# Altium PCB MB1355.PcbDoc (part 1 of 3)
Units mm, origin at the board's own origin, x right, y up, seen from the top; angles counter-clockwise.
Board outline 70.13 x 64.58 mm, 4 copper layers (L1, L2, L3, L4), stack 1.565 mm thick; 213 components, 161 nets, 1280 pads, 261 vias.
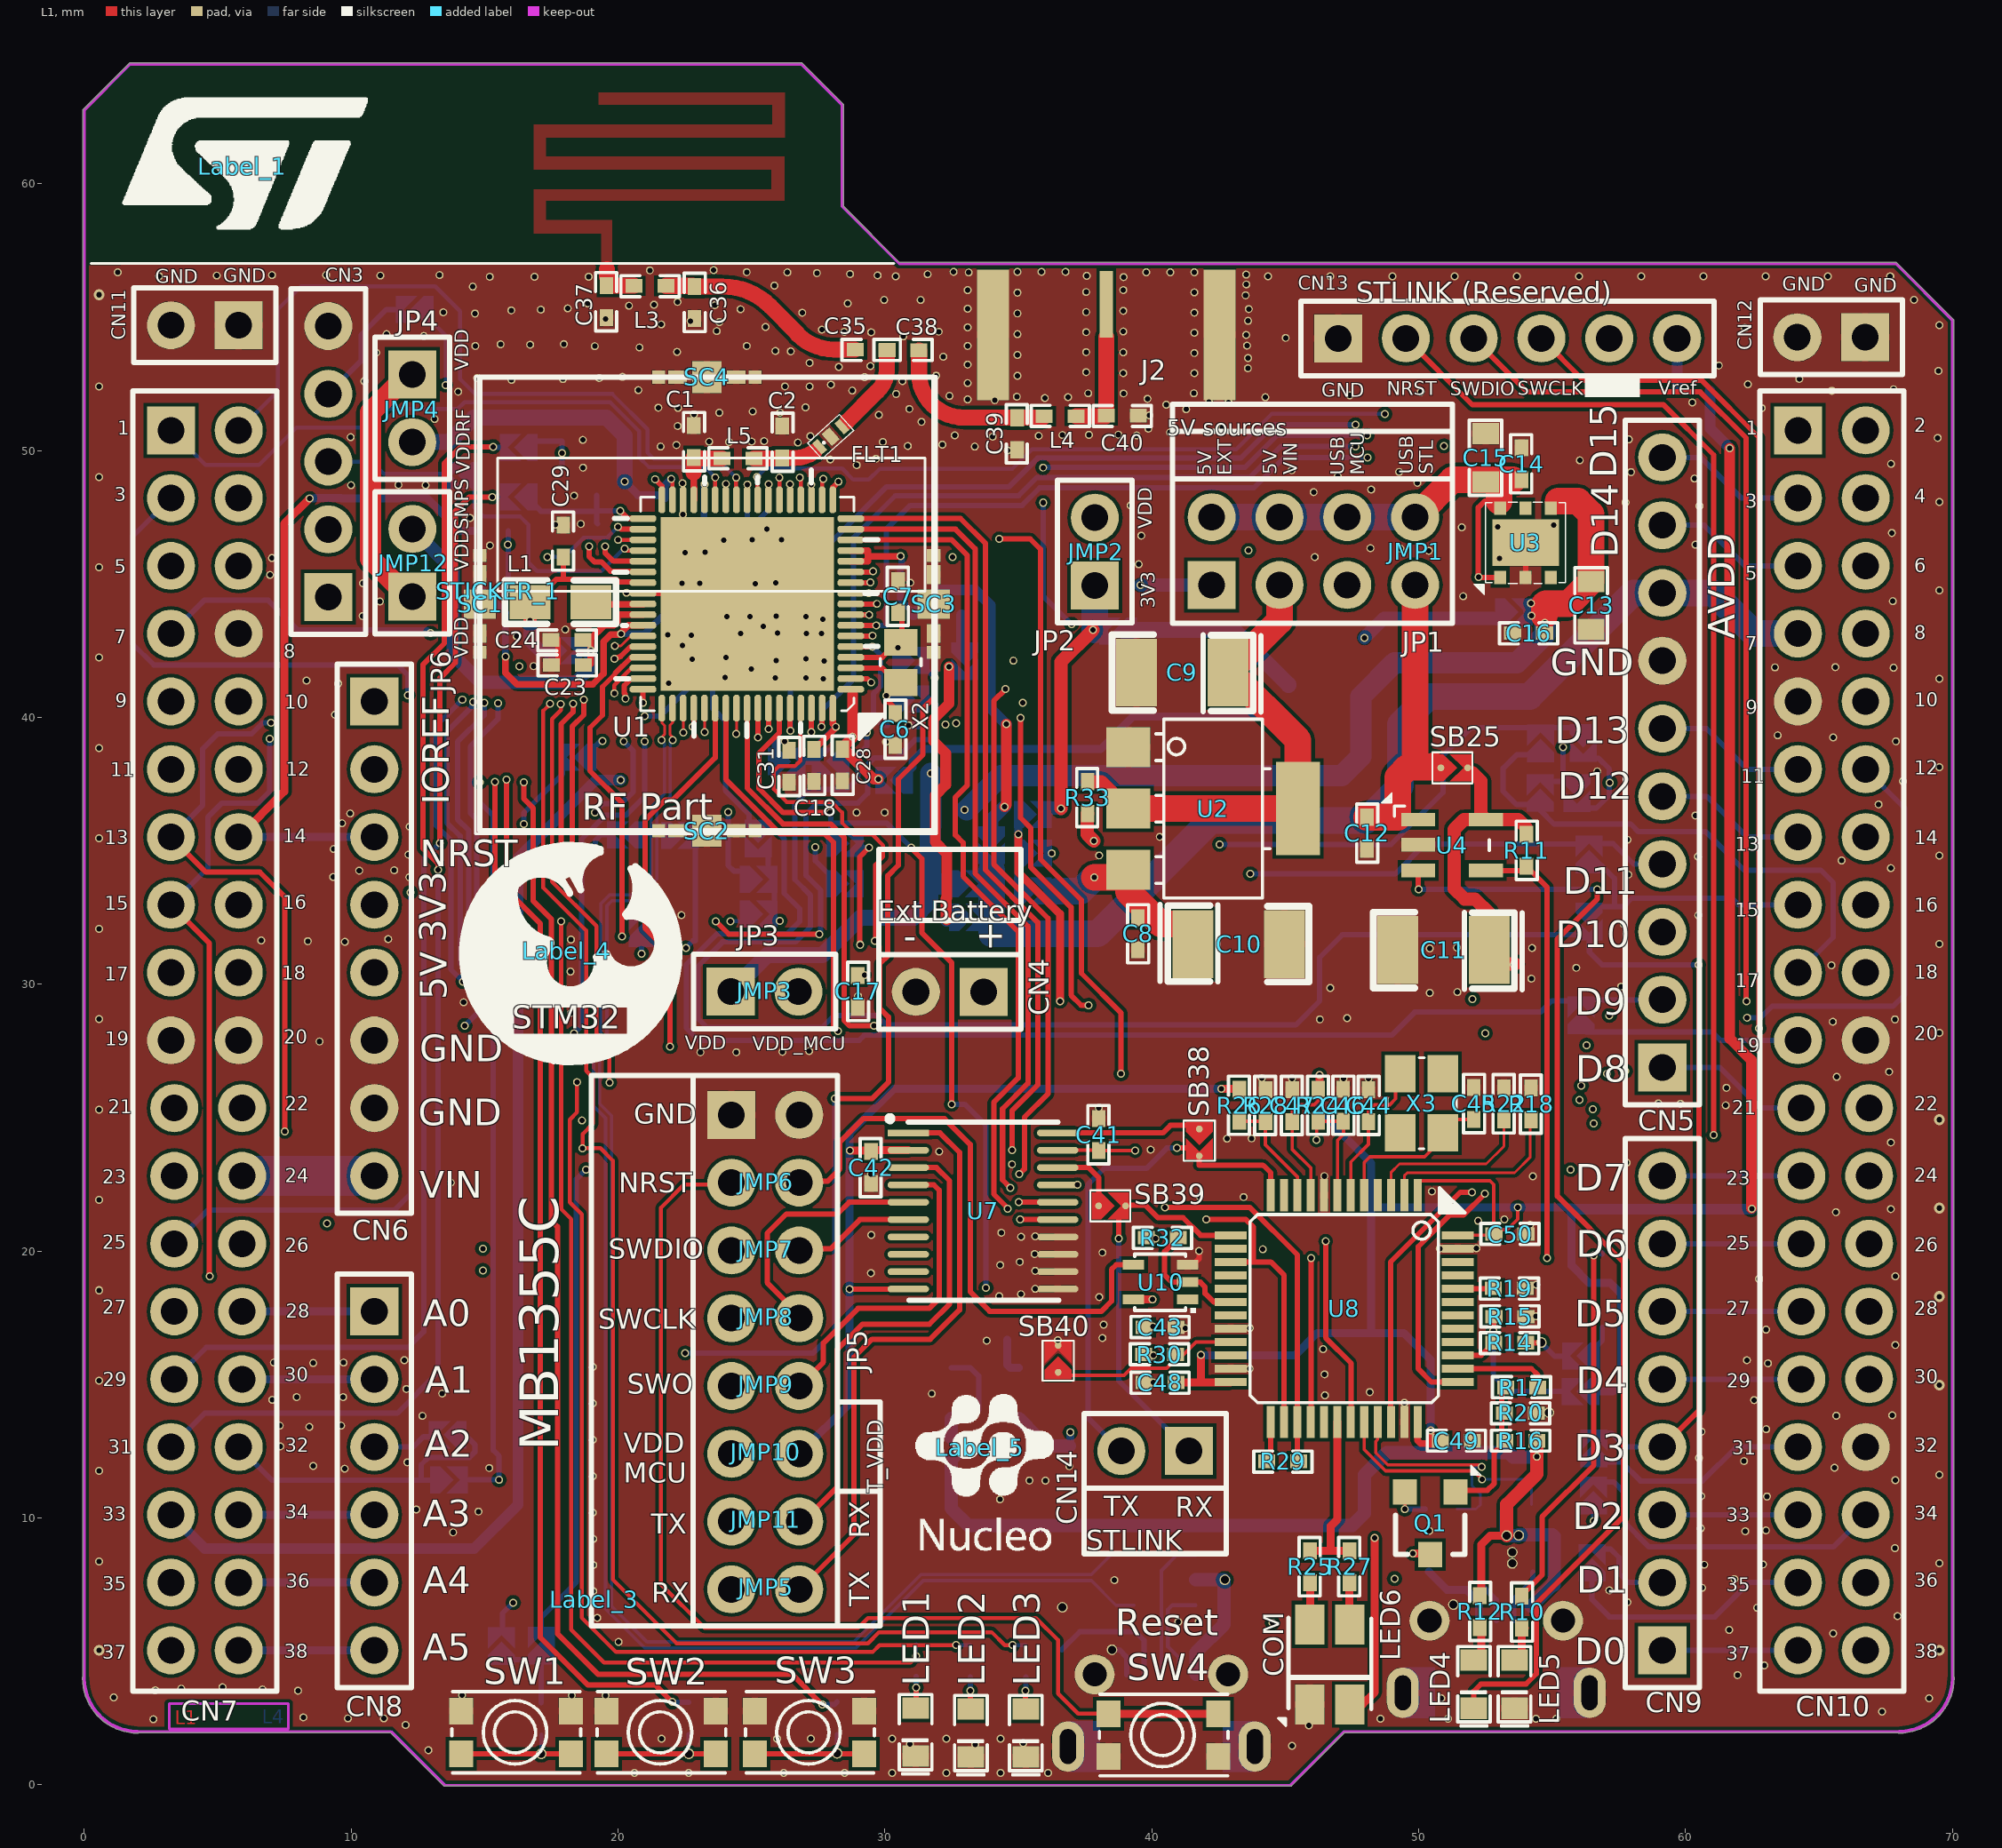
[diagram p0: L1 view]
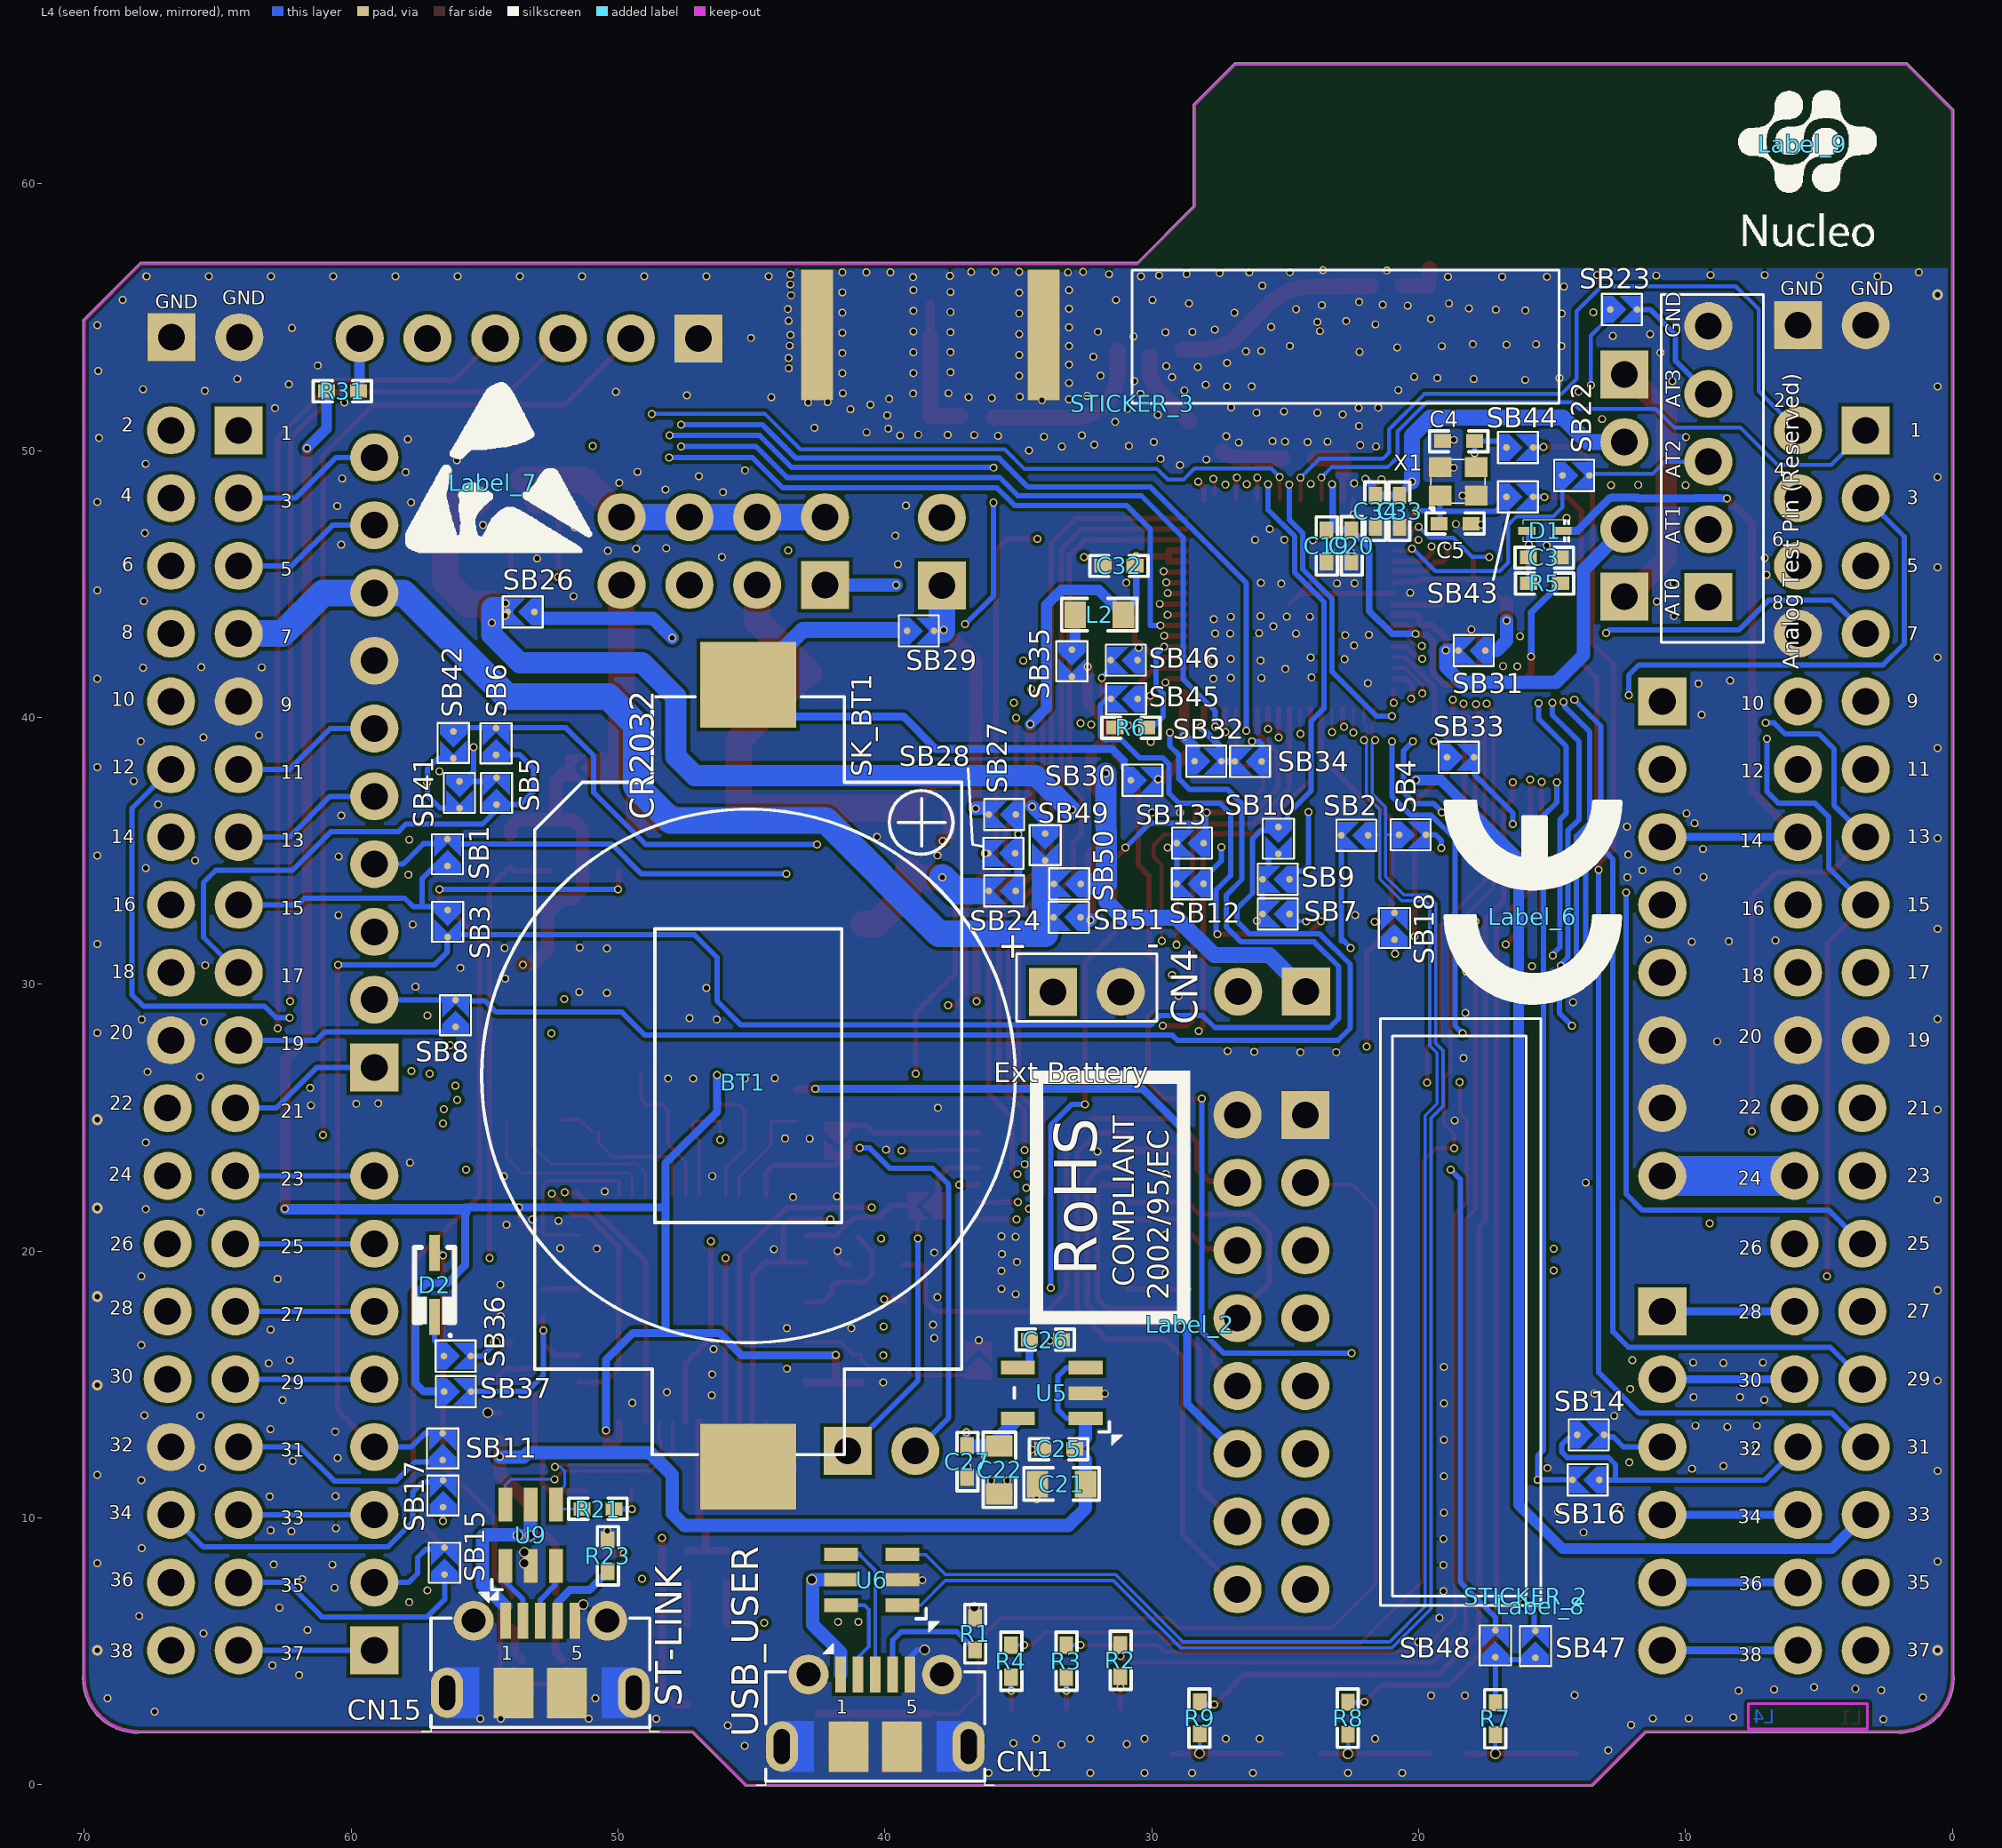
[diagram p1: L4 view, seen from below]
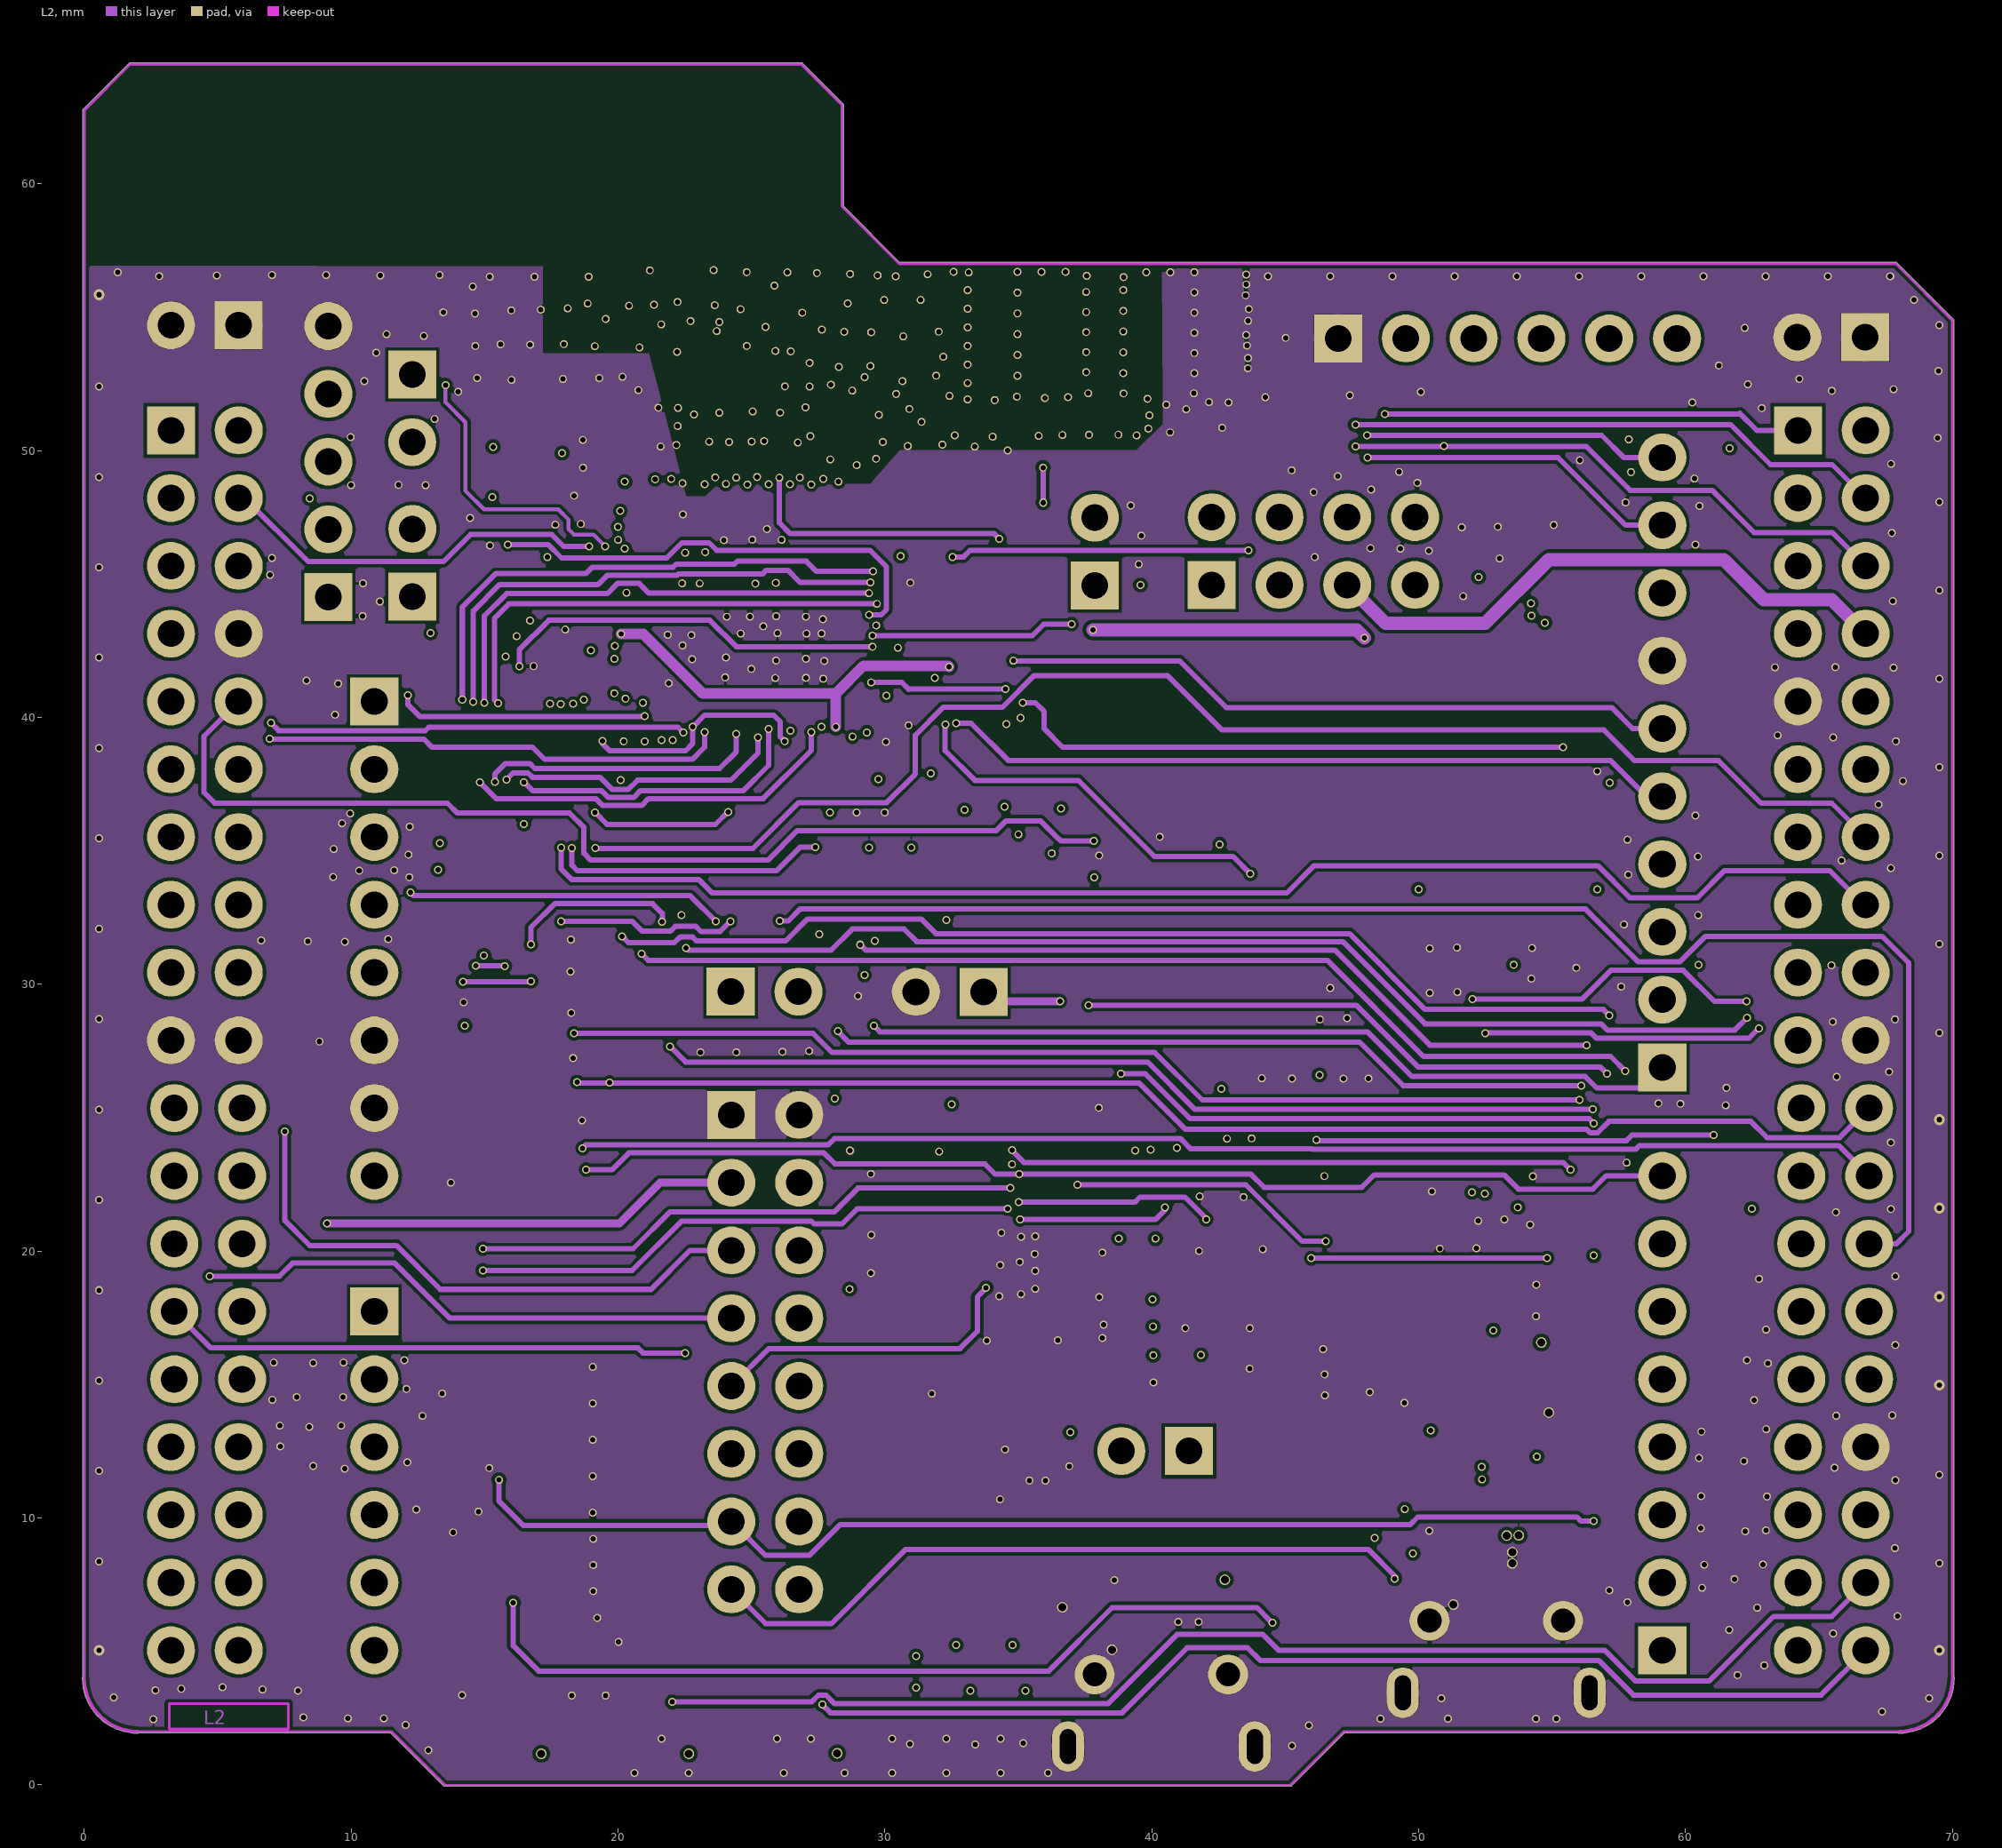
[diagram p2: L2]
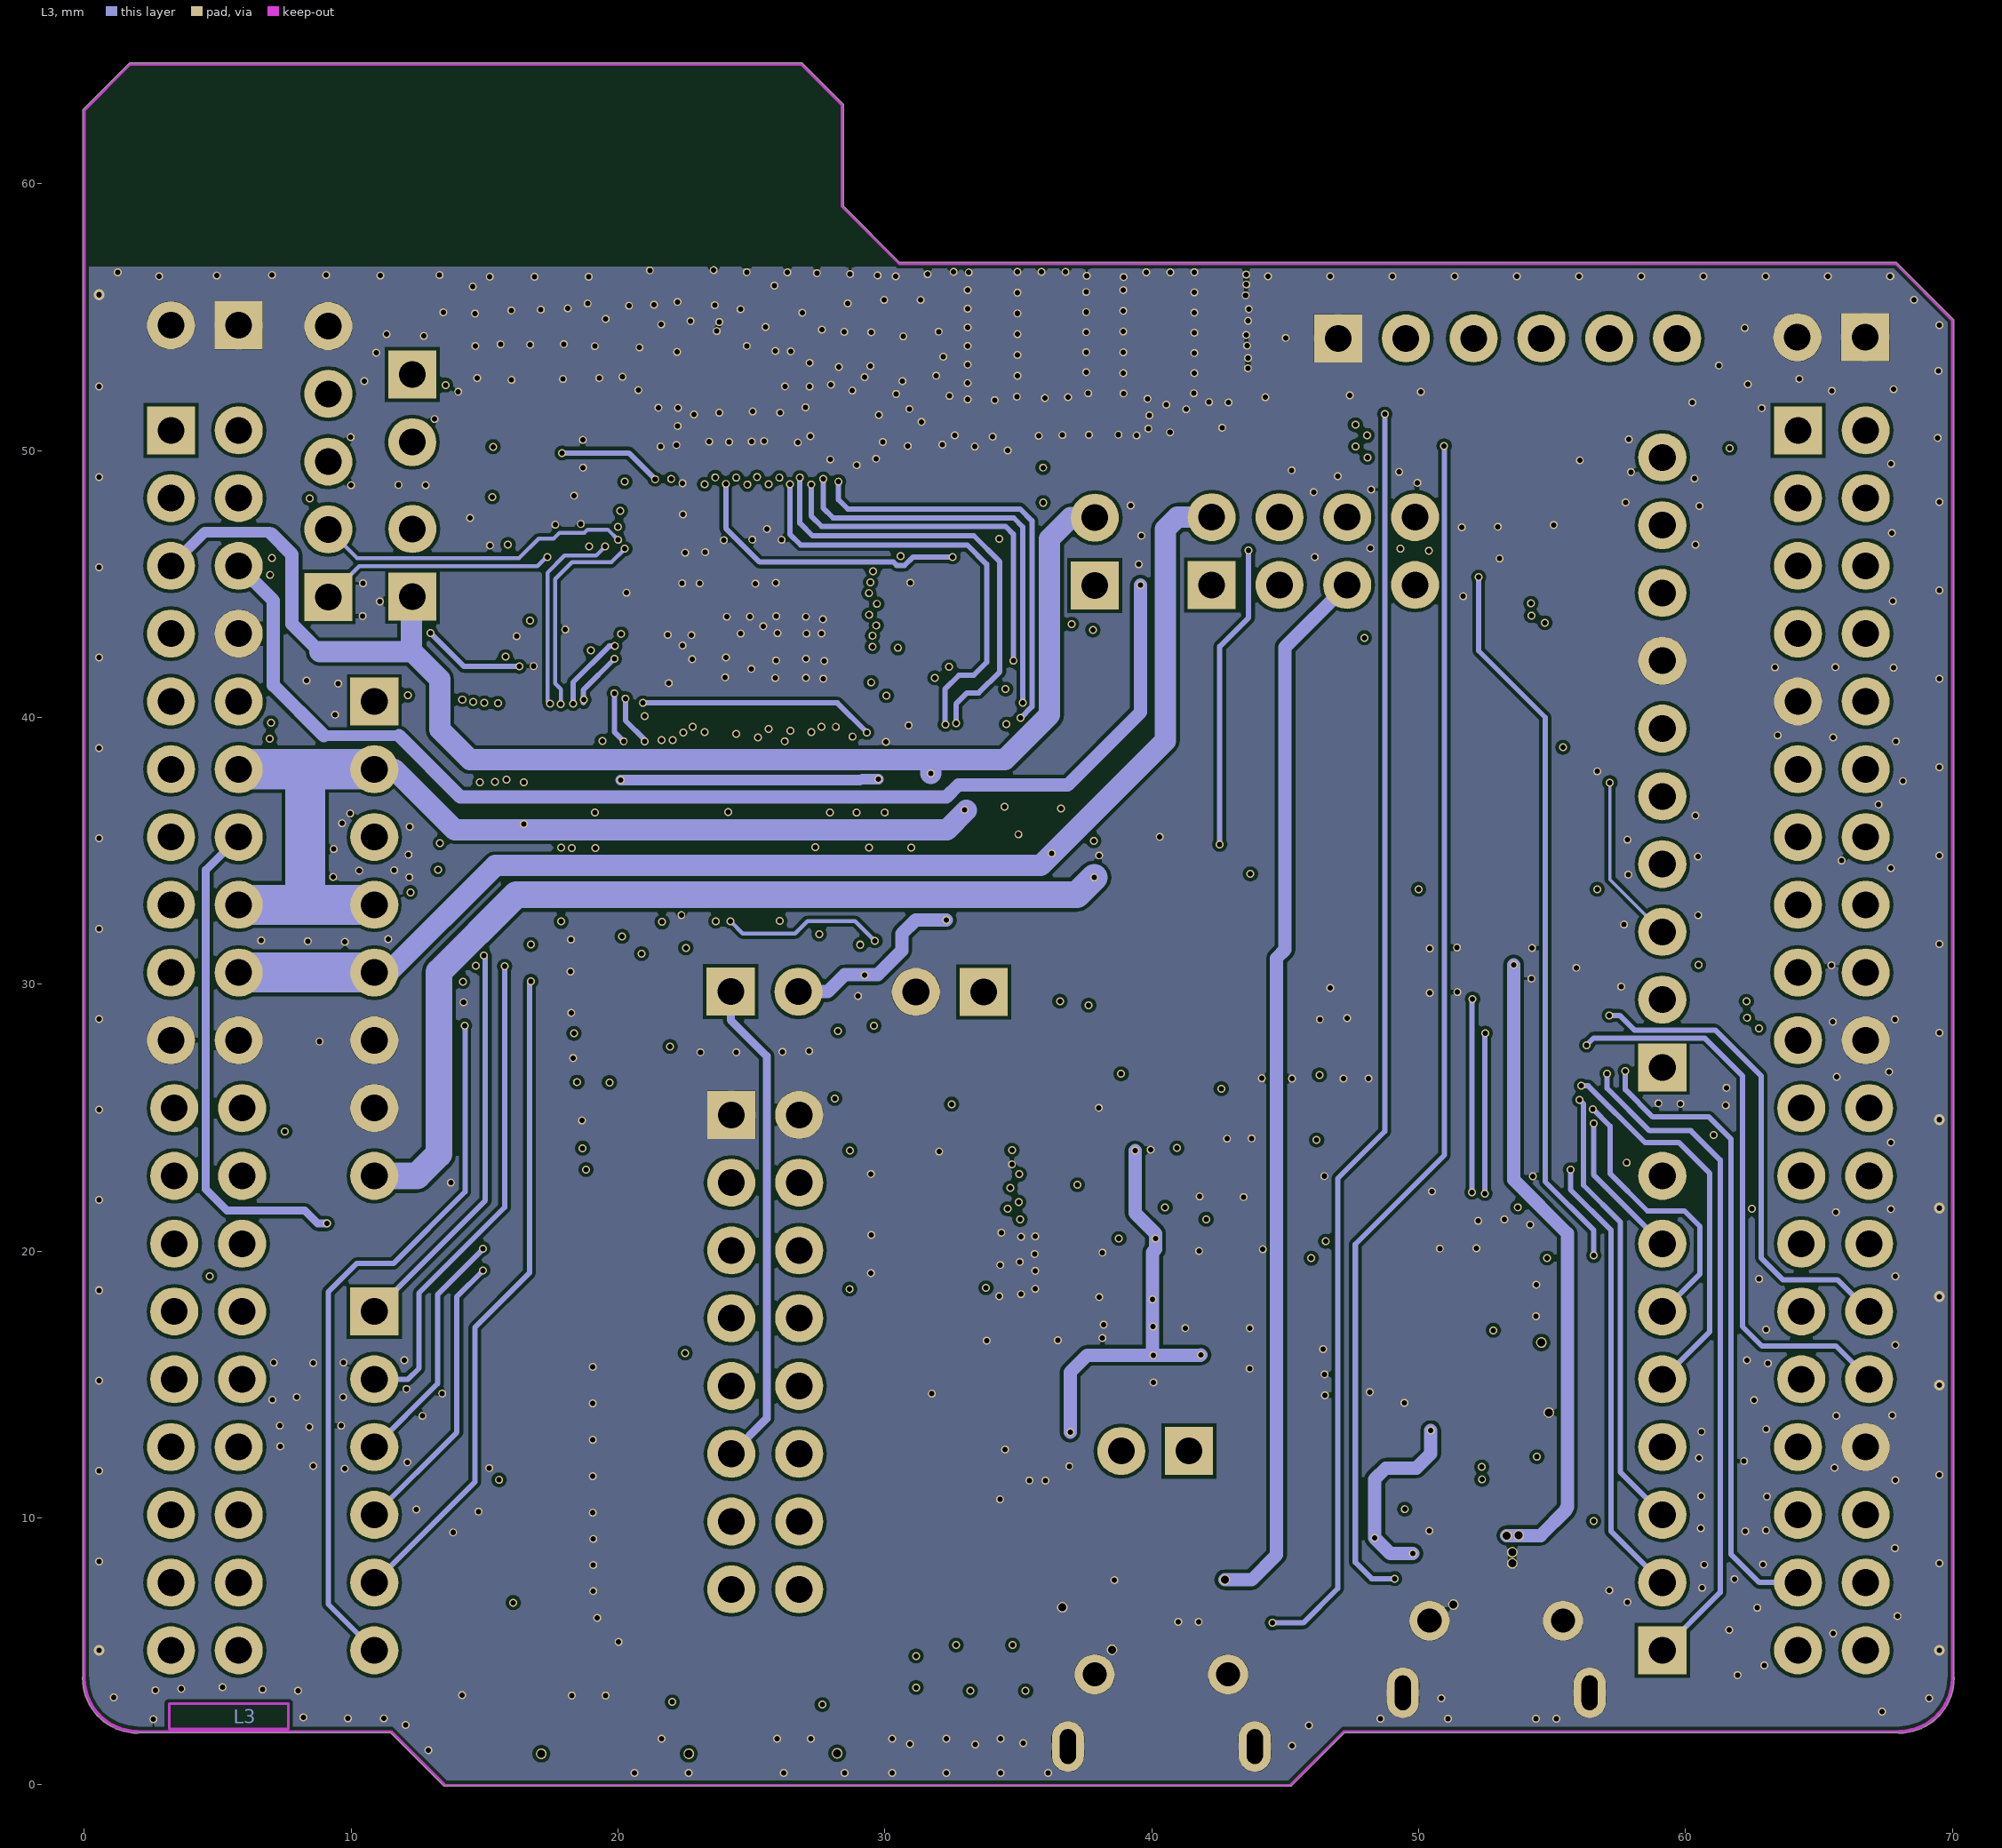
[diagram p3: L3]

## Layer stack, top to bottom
Top Solder: solder mask 0.0178, Solder Resist, Dk 4
L1: signal copper 0.0406
Dielectric1: core 0.4572, FR-4, Dk 4.2
L2: signal copper 0.0305
Dielectric 3: prepreg 0.508, Dk 4.4
L3: signal copper 0.0305
Dielectric 2: core 0.4572, FR-4, Dk 4.2
L4: signal copper 0.0406
Bottom Solder: solder mask 0.0178, Solder Resist, Dk 4

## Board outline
2,1.936 ccw(c2,2) 2.039,1.95 11.479,1.95 13.464,-0.036 13.464,-0.035 ccw(c13.5,0) 13.5,-0.05 45.2,-0.05 ccw(c45.2,0) 45.236,-0.035 45.236,-0.036 47.221,1.95 67.961,1.95 ccw(c68,2) 68,1.936 ccw(c68,4) 70.064,4 ccw(c70,4) 70.05,4.039 70.05,54.876 ccw(c70,54.876) 70.035,54.912 70.036,54.912 67.912,57.036 67.912,57.035 ccw(c67.876,57) 67.876,57.05 30.559,57.05 28.446,59.163 28.446,62.952 ccw(c28.396,62.952) 28.431,62.988 28.432,62.988 26.908,64.512 26.908,64.511 ccw(c26.872,64.476) 26.872,64.526 1.726,64.526 ccw(c1.726,64.476) 1.69,64.511 1.69,64.512 -0.036,62.786 -0.035,62.786 ccw(c0,62.75) -0.05,62.75 -0.05,4.039 ccw(c0,4) -0.064,4 ccw(c2,4)

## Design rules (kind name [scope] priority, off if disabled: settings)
AssemblyTestPointUsage [All] p1 off:
AssemblyTestpoint [All] p1 off: testpointundercomponent=TRUE minsize=1.016 maxsize=2.54 preferedsize=1.524 minholesize=0 maxholesize=1.016 preferedholesize=0.813 testpointgrid=0.025 usegrid=TRUE gridtolerance=0 allowsidetop=TRUE allowsidebottom=TRUE
Clearance 0.126 [All] p1: gap=0.1 ignorepadtopadclearanceinfootprint=FALSE except(0: Arc-Hole Track-Hole SMDPad-Hole THPad-Hole Via-Hole Fill-Hole Poly-Hole Region-Hole Text-Hole; 0.126: Arc-Poly Track-Poly SMDPad-Poly THPad-Poly Via-Poly)
ComponentClearance [All] p1 off: gap=0.254 collisioncheckmode=3 verticalgap=0.254 showdistances=FALSE
DiffPairsRouting [All] p1: maxlimit=0.1 minlimit=0.1 mostfreqgap=0.1 toplayer_minwidth=0.12 toplayer_maxwidth=0.12 toplayer_prefwidth=0.12 midlayer1_minwidth=0.12 midlayer1_maxwidth=0.12 midlayer1_prefwidth=0.12 midlayer4_minwidth=0.12 midlayer4_maxwidth=0.12 midlayer4_prefwidth=0.12 bottomlayer_minwidth=0.12 bottomlayer_maxwidth=0.12 bottomlayer_prefwidth=0.12 maxuncoupledlength=12.7
FabricationTestPointUsage TestPointUsage [All] p1 off: valid=0 allowmultiple=FALSE
FabricationTestpoint Testpoint [(IsPad And (OnTopLayer Or OnBottomLayer))] p1 off: side=3 testpointundercomponent=TRUE minsize=1.016 maxsize=2.54 preferedsize=1.524 minholesize=0 maxholesize=1.016 preferedholesize=0.813 testpointgrid=0.025 allowsidetop=TRUE allowsidebottom=TRUE usegrid=TRUE gridtolerance=0
FanoutControl Fanout_BGA [IsBGA] p1 off: bgadir=Out bgaviamode=Centered fanoutstyle=Auto fanoutdirection=Alternating viagrid=0.025 // Fanout_BGA (Default Rule)
FanoutControl Fanout_LCC [IsLCC] p2 off: bgadir=Out bgaviamode=Centered fanoutstyle=Auto fanoutdirection=Alternating viagrid=0.025 // Fanout_LCC (Default Rule)
FanoutControl Fanout_SOIC [IsSOIC] p3 off: bgadir=Out bgaviamode=Centered fanoutstyle=Auto fanoutdirection=Alternating viagrid=0.025 // Fanout_SOIC (Default Rule)
FanoutControl Fanout_Small [(CompPinCount < 5)] p4 off: bgadir=Out bgaviamode=Centered fanoutstyle=Auto fanoutdirection=OutThenIn viagrid=0.025 // Fanout_Small (Default Rule)
FanoutControl Fanout_Default [All] p5 off: bgadir=Out bgaviamode=Centered fanoutstyle=Auto fanoutdirection=Alternating viagrid=0.025 // Fanout_Default (Default Rule)
Height [All] p1 off: minheight=0 maxheight=25.4 prefheight=12.7
HoleSize [All] p1 off: absolutevalues=TRUE maxlimit=3.81 minlimit=0.1 maxpercent=80.000 minpercent=20.000
HoleToHoleClearance [All] p1 off: gap=0.254 allowstackedmicrovias=TRUE
LayerPairs [All] p1 off: enforce=FALSE
MinimumSolderMaskSliver [All] p1 off: minsoldermaskwidth=0.254
NetAntennae [All] p1 off: netantennaetolerance=0
PlaneClearance [All] p1 off: clearance=0.508
PlaneConnect [All] p1: planeconnectstyle=Direct reliefexpansion=0.508 reliefentries=4 reliefconductorwidth=0.254 reliefairgap=0.254
PolygonConnect [IsVia] p1: connectstyle=Direct reliefconductorwidth=0.508 reliefentries=4 polygonreliefangle="90 Angle" airgapwidth=0.254
RoutingCorners [All] p1 off: cornerstyle=45-Degree minsetback=2.54 maxsetback=2.54
RoutingLayers [All] p1 off: top layer_v5=TRUE mid layer 1_v5=TRUE mid layer 4_v5=TRUE bottom layer_v5=TRUE
RoutingPriority [All] p1 off: routingpriority=0
RoutingTopology [All] p1 off: topology=Shortest
RoutingVias [All] p1: holewidth=0.3 width=0.4 viastyle="Through Hole" minholewidth=0.1 minwidth=0.2 maxholewidth=3.6 maxwidth=6
SilkToBoardRegionClearance [All] p1 off:
SilkToSilkClearance [All] p1 off: silktosilkclearance=0.254
SilkToSolderMaskClearance SilkscreenOverComponentPads [IsPad] p1 off: minsilkscreentomaskgap=0.254 clearancetoexposedcopper=TRUE
SolderMaskExpansion [All] p1: expansion=0.102
Width [All] p1: maxlimit=6 minlimit=0.075 preferedwidth=0.2 midlayer4_minwidth=0.1 bottomlayer_minwidth=0.1 minimp=50.000000 maximp=50.000000 favimp=50.000000
4 further rules are at their usual default settings.

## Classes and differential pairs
component class MCU: C3 C4 C5 C6 C7 CN3 D1 LED1 LED2 LED3 R2 R3 R4 R5 R6 R7 R8 R9 SB22 SB23 SB43 SB44 SB45 SB46 SB47 SB48 SW1 SW2 SW3 SW4 X1 X2
net class DIFF90: USB_N USB_P USBSTLK_N USBSTLK_P
component class ST_LINK_V2-1: C41 C42 C43 C44 C45 C46 C47 C48 C49 C50 CN13 CN14 CN15 D2 JMP5 JMP6 JMP7 JMP8 JMP9 JMP10 JMP11 JP5 LD1 LED6 Q1 R14 R15 R16 R17 R18 R19 R20 R21 R22 R23 R24 R25 R26 R27 R28 R29 R30 R31 R32 SB36 SB37 SB38 SB39 SB40 U7 U8 U9 U10 X3
component class RF: C1 C2 C33 C34 C35 C36 C37 C38 C39 C40 FLT1 J2 J? JMP4 JP4 L3 L4 L5 SC1 SC2 SC3 SC4 SH1 U1
component class Power_managment: BT1 C8 C9 C10 C11 C12 C13 C14 C15 C16 C17 C18 C19 C20 C21 C22 C23 C24 C25 C26 C27 C28 C29 C31 C32 CN4 CN11 CN12 JMP1 JMP2 JMP3 JMP12 JP1 JP2 JP3 JP6 L1 L2 LD3 LED4 LED5 R10 R11 R12 SB24 SB25 SB26 SB27 SB28 SB29 SB30 SB31 SB32 SB33 SB34 SB35 SB49 SB50 SB51 SK_BT1 T2 U2 U3 U4 U5
component class Extension_CN: CN1 CN5 CN6 CN7 CN8 CN9 CN10 R1 R33 SB1 SB2 SB3 SB4 SB5 SB6 SB7 SB8 SB9 SB10 SB11 SB12 SB13 SB14 SB15 SB16 SB17 SB18 SB41 SB42 U6
component class Project_Overview: Label_1 Label_2 Label_3 Label_4 Label_5 Label_6 Label_7 Label_8 Label_9 STICKER_1 STICKER_2 STICKER_3
differential pair USB: +USB_P -USB_N
differential pair USBSTLK: +USBSTLK_P -USBSTLK_N

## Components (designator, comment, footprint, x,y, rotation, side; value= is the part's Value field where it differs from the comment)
BT1 "CR2032-BAT1" CR2032_BAT 45.307,26.32 r270 bottom locked
C1 "0.8pF" 0402_CAP_NPOL 22.836,50.335 r270 top
C2 "0.3pF" 0402_CAP_NPOL 26.156,50.315 r270 top
C3 "100nF" 0402_CAP_NPOL 15.294,45.998 r0 bottom
C4 "TBD" 0402_CAP_NPOL 18.499,50.361 r0 bottom
C5 "TBD" 0402_CAP_NPOL 18.637,47.259 r180 bottom
C6 "10pF" 0402_CAP_NPOL 30.387,39.556 r270 top
C7 "10pF" 0402_CAP_NPOL 30.496,44.535 r90 top
C8 "100nF/25V" 0402_CAP_NPOL 39.48,31.894 r270 top
C9 "10uF/25V" 1210_CAP_POL 41.142,41.684 r180 top
C10 "10uF/25V" 1210_CAP_POL 43.26,31.504 r0 top
C11 "4.7uF/10V" 1210_CAP_POL 50.93,31.284 r180 top
C12 "100nF" 0402_CAP_NPOL 48.057,35.664 r270 top
C13 "1uF/X5R" 0603_CAP_NPOL 56.46,44.198 r270 top
C14 "100nF" 0402_CAP_NPOL 53.852,49.505 r90 top
C15 "1uF/X5R" 0603_CAP_NPOL 52.507,49.731 r90 top
C16 "100nF" 0402_CAP_NPOL 54.119,43.161 r180 top
C17 "100nF" 0402_CAP_NPOL 28.985,29.732 r270 top
C18 "100nF" 0402_CAP_NPOL 27.344,38.203 r270 top
C19 "100nF" 0402_CAP_NPOL 23.455,46.427 r270 bottom
C20 "100nF" 0402_CAP_NPOL 22.521,46.429 r270 bottom
C21 "1uF/X5R" 0603_CAP_NPOL 33.38,11.274 r0 bottom
C22 "1uF/X5R" 0603_CAP_NPOL 35.71,11.804 r270 bottom
C23 "4.7uF" 0402_CAP_NPOL 18.1,41.964 r180 top
C24 "100nF" 0402_CAP_NPOL 18.091,42.902 r180 top
C25 "100nF" 0402_CAP_NPOL 33.49,12.594 r0 bottom
C26 "100nF" 0402_CAP_NPOL 33.99,16.674 r180 bottom
C27 "100nF" 0402_CAP_NPOL 36.92,12.114 r270 bottom
C28 "100nF" 0402_CAP_NPOL 28.41,38.212 r270 top
C29 "4.7uF" 0402_CAP_NPOL 17.951,46.609 r90 top
C31 "100nF" 0402_CAP_NPOL 26.409,38.163 r270 top
C32 "100nF" 0402_CAP_NPOL 31.23,45.689 r0 bottom
C33 "100nF" 0402_CAP_NPOL 20.715,47.726 r90 bottom
C34 "100pF" 0402_CAP_NPOL 21.612,47.726 r90 bottom
C35 "10nF" 0402_CAP_NPOL 29.488,53.783 r180 top
C36 "" 0402_CAP_NPOL 22.863,55.551 r270 top
C37 "1.2pF" 0402_CAP_NPOL 19.566,55.578 r90 top
C38 "" 0402_CAP_NPOL 30.679,53.759 r0 top
C39 "" 0402_CAP_NPOL 34.957,50.63 r90 top
C40 "" 0402_CAP_NPOL 38.895,51.31 r180 top
C41 "100nF" 0402_CAP_NPOL 38.011,24.365 r90 top
C42 "100nF" 0402_CAP_NPOL 29.478,23.131 r90 top
C43 "100nF" 0402_CAP_NPOL 40.31,17.146 r0 top
C44 "20pF" 0402_CAP_NPOL 48.12,25.456 r270 top
C45 "20pF" 0402_CAP_NPOL 52.064,25.532 r270 top
C46 "100nF" 0402_CAP_NPOL 47.17,25.466 r270 top
C47 "100nF" 0402_CAP_NPOL 45.26,25.456 r90 top
C48 "100nF" 0402_CAP_NPOL 40.31,15.076 r180 top
C49 "100nF" 0402_CAP_NPOL 51.414,12.886 r0 top
C50 "100nF" 0402_CAP_NPOL 53.42,20.636 r0 top
CN1 "1050170001" USBMICROB_MOLEX_105017-0001_H2P90 40.359,-0.015 r180 bottom
CN3 "HEADER_1X5" "Header NF 1x5x2.54 TH" 9.146,44.507 r90 top
CN4 "HEADER_1X2" "Header NF 1x2x2.54 TH" 33.703,29.714 r180 top
CN5 "HEADER_1X10" "Header F 1x10x2.54 TH V" 59.13,26.884 r90 top locked
CN6 "HEADER_1X8_F" "Header F 1x8x2.54 TH V" 10.87,40.6 r270 top locked (schematic designator CN8)
CN7 "HEADER_2X19_M" "Header M 2x19x2.54 TH M_top + M_bottom" 3.25,50.76 r270 top locked (schematic designator CN9)
CN8 "HEADER_1X6" "Header F 1x6x2.54 TH V" 10.87,17.74 r270 top locked (schematic designator CN14)
CN9 "HEADER_1X8_F" "Header F 1x8x2.54 TH V" 59.13,5.04 r90 top locked (schematic designator CN11)
CN10 "HEADER_2X19_M" "Header M 2x19x2.54 TH M_top + M_bottom" 64.21,50.76 r270 top locked
CN11 "HEADER_1X2" "Header M 1x2x2.54 TH V" 5.79,54.697 r180 top
CN12 "HEADER_1X2" "Header M 1x2x2.54 TH V" 66.73,54.244 r180 top
CN13 "HEADER_1X6" "Header NF 1x6x2.54 TH" 46.98,54.204 r0 top
CN14 "HEADER_1X2" "Header NF 1x2x2.54 TH" 41.398,12.509 r180 top
CN15 "1050170001" USBMICROB_MOLEX_105017-0001_H2P90 52.907,2 r180 bottom
D1 "BAT54KFILM" SOD523 15.27,46.998 r180 bottom
D2 "BAT60JFILM" SOD-323 56.87,18.734 r270 bottom
FLT1 "LFB182G45CGFD436" LFB182G45CGFD436 27.968,50.52 r42 top
J2 "SMA" SMA_T_9.52_NF 38.298,57.894 r90 top
JMP1 "Jumper 2.54mm" "Jumper 2.54mm BLACK" 49.871,46.225 r270 top
JMP2 "Jumper 2.54mm" "Jumper 2.54mm BLACK" 37.897,46.196 r90 top
JMP3 "Jumper 2.54mm" "Jumper 2.54mm BLACK" 25.482,29.761 r0 top
JMP4 "Jumper 2.54mm" "Jumper 2.54mm BLACK" 12.269,51.546 r270 top
JMP5 "Jumper 2.54mm" "Jumper 2.54mm BLACK" 25.538,7.412 r180 top
JMP6 "Jumper 2.54mm" "Jumper 2.54mm BLACK" 25.538,22.599 r180 top
JMP7 "Jumper 2.54mm" "Jumper 2.54mm BLACK" 25.538,20.068 r180 top
JMP8 "Jumper 2.54mm" "Jumper 2.54mm BLACK" 25.538,17.537 r180 top
JMP9 "Jumper 2.54mm" "Jumper 2.54mm BLACK" 25.538,15.005 r180 top
JMP10 "Jumper 2.54mm" "Jumper 2.54mm BLACK" 25.538,12.474 r180 top
JMP11 "Jumper 2.54mm" "Jumper 2.54mm BLACK" 25.538,9.943 r180 top
JMP12 "Jumper 2.54mm" "Jumper 2.54mm BLACK" 12.339,45.779 r90 top
JP1 "HEADER_2X4" "Header M 2x4x2.54 TH V" 42.245,44.965 r0 top
JP2 "HEADER_1X2" "Header M 1x2x2.54 TH V" 37.867,44.946 r90 top
JP3 "HEADER_1X2" "Header M 1x2x2.54 TH V" 24.222,29.723 r0 top
JP4 "HEADER_1X2" "Header M 1x2x2.54 TH V" 12.289,52.856 r270 top
JP5 "HEADER_2X8" "Header M 2x8x2.54 TH V" 24.247,25.107 r270 top
JP6 "HEADER_1X2" "Header M 1x2x2.54 TH V" 12.296,44.523 r90 top
L1 "10uH" 0805_COIL 16.702,44.318 r0 top
L2 "FCM1608KF-601T03" 0603_COIL 31.965,43.852 r180 bottom
L3 "3.6nH" 0402_COIL 21.201,56.173 r180 top
L4 "0R" 0402_COIL 36.57,51.289 r0 top
L5 "2.7nH" 0402_COIL 24.495,49.703 r0 top
Label_1 "LOGO_ST" LOGO_ST_Size3 5.925,60.67 r0 top
Label_2 "LOGO_ROHS" SYMBOL_RoHS 28.564,17.265 r90 bottom
Label_3 "LOGO_Nucleo_www" LOGO_Nucleo_www 19.111,6.957 r90 top
Label_4 "LOGO_STM32" LOGO_STM32 18.074,31.267 r0 top
Label_5 "LOGO_Nucleo" LOGO_Nucleo 33.559,12.655 r0 top
Label_6 "LOGO_CE" "LOGO CE" 15.724,32.546 r90 bottom
Label_7 "LOGO_ESD" "LOGO ESD" 54.689,48.818 r180 bottom
Label_8 "LOGO_StickerArea_W21x6" LOGO_StickerArea_Border 15.425,6.72 r90 bottom
Label_9 "LOGO_Nucleo" LOGO_Nucleo 5.609,61.504 r180 bottom
LED1 "LED BLUE" 0603_LED_Blue 31.15,1.974 r90 top
LED2 "LED GREEN" 0603_LED_GREEN 33.22,1.944 r90 top
LED3 "LED RED" 0603_LED_RED 35.28,1.944 r90 top
LED4 "LED RED" 0603_LED_RED 52.069,3.77 r90 top
LED5 "LED RED" 0603_LED_RED 53.593,3.77 r90 top
LED6 "HSMF-A201-A00J1/KAA-3528SURKCGKC" HSMF-A201 46.67,4.514 r90 top
Q1 "2N2222" SOT23-3 50.432,8.629 r180 top
R1 "100K" 0402_RES 36.627,5.66 r270 bottom
R2 "680" 0402_RES 31.175,4.664 r270 bottom
R3 "680" 0402_RES 33.205,4.634 r270 bottom
R4 "680" 0402_RES 35.275,4.634 r270 bottom
R5 "100K (not fitted)" 0402_RES 15.282,45.028 r0 bottom
R6 "10K" 0402_RES 30.781,39.629 r0 bottom
R7 "1K" 0402_RES 17.124,2.478 r90 bottom
R8 "1K" 0402_RES 22.646,2.496 r90 bottom
R9 "1K" 0402_RES 28.203,2.504 r90 bottom
R10 "1K" 0402_RES 53.863,6.476 r270 top
R11 "10K" 0402_RES 54.034,35.021 r270 top
R12 "1K" 0402_RES 52.29,6.495 r270 top
R14 "2K7" 0402_RES 53.41,16.566 r180 top
R15 "4K7" 0402_RES 53.42,17.546 r0 top
R16 "10K" 0402_RES 53.826,12.886 r0 top
R17 "100" 0402_RES 53.856,14.889 r0 top
R18 "10K" 0402_RES 54.214,25.512 r90 top
R19 "100K" 0402_RES 53.4,18.606 r180 top
R20 "36K" 0402_RES 53.816,13.933 r180 top
R21 "1K5" 0402_RES 50.75,10.334 r180 bottom
R22 "10K" 0402_RES 53.194,25.522 r90 top
R23 "100K" 0402_RES 50.39,8.584 r270 bottom
R24 "100K" 0402_RES 46.24,25.466 r90 top
R25 "100/2K7" 0402_RES 45.93,8.174 r90 top
R26 "4K7" 0402_RES 43.28,25.466 r90 top
R27 "100/100" 0402_RES 47.41,8.174 r90 top
R28 "4K7" 0402_RES 44.26,25.456 r90 top
R29 "100" 0402_RES 44.91,12.126 r180 top
R30 "" 0402_RES 40.29,16.126 r0 top
R31 "10" 0402_RES 60.326,52.233 r0 bottom
R32 "100K" 0402_RES 40.4,20.506 r180 top
R33 "1K" 0402_RES 37.593,36.995 r90 top
SB1 "Close" SB-tiny 56.39,34.934 r90 bottom
SB2 "Open" SB-tiny 22.394,35.586 r0 bottom
SB3 "Open" SB-tiny 56.381,32.281 r270 bottom
SB4 "Open" SB-tiny 20.234,35.604 r180 bottom
SB5 "Close" SB-tiny 54.55,37.234 r90 bottom
SB6 "Open" SB-tiny 54.57,39.094 r90 bottom
SB7 "Open" SB-tiny 25.34,32.633 r0 bottom
SB8 "Close" SB-tiny 56.09,28.904 r90 bottom
SB9 "Close" SB-tiny 25.34,33.937 r0 bottom
SB10 "Open" SB-tiny 25.256,35.395 r270 bottom
SB11 "Close" SB-tiny 56.571,12.669 r90 bottom
SB12 "Close" SB-tiny 28.561,33.767 r0 bottom
SB13 "Open" SB-tiny 28.558,35.288 r0 bottom
SB14 "Close" SB-tiny 13.559,13.115 r180 bottom
SB15 "Close" SB-tiny 56.504,8.384 r90 bottom
SB16 "Open" SB-tiny 13.731,11.429 r0 bottom
SB17 "Close" SB-tiny 56.556,10.905 r90 bottom
SB18 "Open" SB-tiny 20.905,32.171 r90 bottom
SB22 "Open" SB-tiny 14.11,49.069 r180 bottom
SB23 "Open" SB-tiny 12.321,55.287 r180 bottom
SB24 "Open" SB-tiny 35.597,33.5 r0 bottom
SB25 "Open" SB-tiny 51.331,38.11 r0 top
SB26 "Close" SB-tiny 53.631,43.954 r0 bottom
SB27 "Open" SB-tiny 35.597,36.361 r0 bottom
SB28 "Open" SB-tiny 35.619,34.908 r0 bottom
SB29 "Open" SB-tiny 38.668,43.245 r180 bottom
SB30 "Open" SB-tiny 30.284,37.648 r180 bottom
SB31 "Open" SB-tiny 18.002,42.506 r0 bottom
SB32 "Close" SB-tiny 27.896,38.358 r180 bottom
SB33 "Close" SB-tiny 18.435,38.505 r180 bottom
SB34 "Open" SB-tiny 26.384,38.352 r0 bottom
SB35 "Close" SB-tiny 32.994,42.039 r270 bottom
SB36 "Close" SB-tiny 56.023,16.067 r180 bottom
SB37 "Open" SB-tiny 56.011,14.739 r180 bottom
SB38 "Close" SB-tiny 41.78,24.076 r270 top
SB39 "Close" SB-tiny 38.51,21.696 r0 top
SB40 "Open" SB-tiny 36.493,15.96 r90 top
SB41 "Close" SB-tiny 55.94,37.104 r270 bottom
SB42 "Open" SB-tiny 56.17,38.976 r270 bottom
SB43 "Open" SB-tiny 16.214,48.268 r180 bottom
SB44 "Open" SB-tiny 16.214,50.119 r180 bottom
SB45 "Open" SB-tiny 31.025,40.698 r0 bottom
SB46 "Open" SB-tiny 31.035,42.147 r0 bottom
SB47 "Close" SB-tiny 15.625,5.262 r90 bottom
SB48 "Open" SB-tiny 17.124,5.285 r90 bottom
SB49 "Open" SB-tiny 33.994,35.149 r270 bottom
SB50 "Close" SB-tiny 33.16,33.761 r0 bottom
SB51 "Open" SB-tiny 33.17,32.509 r0 bottom
SC1 "Shield Clip_A 3.9x1.1x1.28" "Shield Clip_A 3.9x1.1x1.28" 14.829,44.252 r90 top locked
SC2 "Shield Clip_A 3.9x1.1x1.28" "Shield Clip_A 3.9x1.1x1.28" 23.329,35.752 r180 top
SC3 "Shield Clip_A 3.9x1.1x1.28" "Shield Clip_A 3.9x1.1x1.28" 31.829,44.252 r90 top
SC4 "Shield Clip_A 3.9x1.1x1.28" "Shield Clip_A 3.9x1.1x1.28" 23.329,52.752 r180 top locked
SH1 "Shield 17.2x17.2x3" "Shield 17.2x17.2x3" -3.147,7.035 r0 top
SK_BT1 "CR2032-SCK1B" CR2032-SCK1 45.12,26.574 r90 bottom locked
STICKER_1 "FCC_ID_Sticker_16x5" "Sticker_FCC_ID 16x5mm" 15.497,44.728 r0 top
STICKER_2 "Sticker_BrdRef_21x5" Sticker_BrdRef_21x5mm 15.978,7.065 r90 bottom
STICKER_3 "Sticker_CPN_FG 16x5" "Sticker_CPN_FG 16x5mm" 30.737,51.764 r180 bottom
SW1 "User PB" "SW-PB SMD KMR2" 16.18,1.967 r0 top
SW2 "User PB" "SW-PB SMD KMR2" 21.614,1.967 r0 top
SW3 "User PB" "SW-PB SMD KMR2" 27.177,1.967 r0 top
SW4 "Reset PB" "SW-PB SMD KMR2" 40.436,1.865 r0 top
U1 "STM32WBxx_QFN68" VFQFPN68_8x8x0.1_p0.4 24.844,44.252 r180 top
U2 "LD1117S50TR" SOT223_SC73_A 42.3,36.584 r270 top
U3 "LD39050PU33R" "DFN6 3x3mm" 54.006,46.549 r0 top
U4 "STMPS2141STR" SOT23-5 51.253,35.217 r0 top
U5 "LD3985M33R" SOT23-5 33.75,14.684 r0 bottom
U6 "USBLC6-2SC6" SOT23-6 39.341,6.734 r0 bottom
U7 "TXS0108EPW" TSSOP20 30.875,24.431 r0 top
U8 "STM32F103CBT6" LQFP48_7X7_P050 47.21,17.846 r180 top
U9 "USBLC6-2SC6" SOT23-6 54.22,8.204 r90 bottom
U10 "74LVC1G07" SOT353-1 41.27,18.186 r180 top
X1 "NX2016_32M" NX2016_4P 18.526,48.848 r180 bottom
X2 "NX2012_32K768" NX2012_2P 30.591,41.307 r90 top
X3 "X3225-8MHz" X3225 50.11,25.542 r270 top

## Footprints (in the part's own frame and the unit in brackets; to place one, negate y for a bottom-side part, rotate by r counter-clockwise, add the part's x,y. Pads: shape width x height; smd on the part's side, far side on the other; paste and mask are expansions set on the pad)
0402_CAP_NPOL [mil] "Capacitor FootPrint 0402"
  rect 25x20 smd: 1(-23.58,0) 2(23.58,0)
  silkscreen extent -43,-15 43,16, body extent -39,-14 41,14, height 32
0402_COIL [mil] "Coil FootPrint 0402"
  rect 25x20 smd: 1(-23.58,0) 2(23.58,0)
  silkscreen extent -43,-15 43,16, body extent -38,-11 39,13, height 16
0402_RES [mil] "Resistor FootPrint 0402"
  rect 25x20 smd: 1(-23.58,0) 2(23.58,0)
  silkscreen extent -43,-15 43,16, body extent -38,-11 39,13, height 16
0603_CAP_NPOL [mm] "Capacitor FootPrint 0603"
  rect 0.8x1 smd: 1(-0.902,0) 2(0.902,0)
  silkscreen extent -1.41,-0.61 1.41,0.61, body extent -1.28,-0.46 1.26,0.48, height 0.82
0603_COIL [mm] "Coil Footprint 0603"
  rect 0.8x1 smd: 1(-0.902,0) 2(0.902,0)
  silkscreen extent -1.41,-0.61 1.41,0.61, body extent -1.26,-0.48 1.26,0.48, height 0.4
0603_LED_Blue [mm] "Resistor Footprint 0603"
  rect 0.8x1 smd: A(0.902,0) K(-0.902,0)
  silkscreen extent -1.59,-0.61 1.41,0.61, body extent -1.26,-0.48 1.26,0.48, height 0.84
0603_LED_GREEN [mm] "Resistor Footprint 0603"
  rect 0.8x1 smd: A(0.902,0) K(-0.902,0)
  silkscreen extent -1.59,-0.61 1.41,0.61, body extent -1.26,-0.48 1.26,0.48, height 0.84
0603_LED_RED [mm] "Resistor Footprint 0603"
  rect 0.8x1 smd: A(0.902,0) K(-0.902,0)
  silkscreen extent -1.59,-0.61 1.41,0.61, body extent -1.26,-0.48 1.26,0.48, height 0.84
0805_COIL [mil] "Coil FootPrint 0805"
  rect 60x50 smd: 1(0,0) 2(90,0)
  silkscreen extent -37,-32 127,32, body extent -21,-25 113,25, height 16
1210_CAP_POL [mil] "Capacitor Polarized 1210"
  rect 60x100 smd: 1(-67.5,0) 2(67.5,0)
  silkscreen extent -116,-56 104,59, body extent -72,-57 73,58, height 80
CR2032-SCK1 [mm]
  rect 3.2x3.6 smd: 1(14.65,0) 2(-14.65,0)
  silkscreen extent -14.2,-10.01 14.2,9.99, body extent -16.1,-8 16.1,8, height 5.6
CR2032_BAT [mm] "CR2032 Lithium Battery"
  body extent -10.25,-9.75 9.75,10.25, height 5.3
"DFN6 3x3mm" [mm] "DFN6 3x3mm heigh=0.8mm"
  rect 0.45x0.5 smd mask+0.02: 1(-0.95,-1.3) 2(0,-1.3) 3(0.95,-1.3) 4(0.95,1.3) 5(0,1.3) 6(-0.95,1.3)
  rect 2.5x1.75 smd mask+0.02: 7(0,0)
  silkscreen extent -1.93,-1.94 1.5,1.52, body extent -1.52,-1.52 1.52,1.52, height 0.9
"Header F 1x6x2.54 TH V" [mm] "1x6x2.54 Header TH V Female"
  rect 1.8x1.8 hole 1: 1(0,0)
  round 1.8 hole 1: 2(2.54,0) 3(5.08,0) 4(7.62,0) 5(10.16,0) 6(12.7,0)
  silkscreen extent -1.4,-1.4 14.1,1.4, body extent -1.42,-1.28 14.07,1.22, height 8.5
"Header F 1x8x2.54 TH V" [mm] "1x8x2.54 Header TH V Female"
  rect 1.8x1.8 hole 1: 1(0,0)
  round 1.8 hole 1: 2(2.54,0) 3(5.08,0) 4(7.62,0) 5(10.16,0) 6(12.7,0) 7(15.24,0) 8(17.78,0)
  silkscreen extent -1.4,-1.4 19.18,1.4, body extent -1.42,-1.35 19.15,1.15, height 8.5
"Header F 1x10x2.54 TH V" [mm] "1x10x2.54 Header TH V Female"
  rect 1.8x1.8 hole 1: 1(0,0)
  round 1.8 hole 1: 2(2.54,0) 3(5.08,0) 4(7.62,0) 5(10.16,0) 6(12.7,0) 7(15.24,0) 8(17.78,0) 9(20.32,0) 10(22.86,0)
  silkscreen extent -1.4,-1.4 24.26,1.4, body extent -1.42,-1.33 24.23,1.17, height 8.5
"Header M 1x2x2.54 TH V" [mm] "1x2x2.54 Header TH V Male"
  rect 1.8x1.8 hole 1: 1(0,0)
  round 1.8 hole 1: 2(2.54,0)
  silkscreen extent -1.4,-1.4 3.94,1.4, body extent -1.27,-1.27 3.81,1.27, height 8.55
"Header M 2x4x2.54 TH V" [mm] "2x4x2.54 Header TH V Male"
  rect 1.8x1.8 hole 1: 1(0,0)
  round 1.8 hole 1: 2(0,2.54) 3(2.54,0) 4(2.54,2.54) 5(5.08,0) 6(5.08,2.54) 7(7.62,0) 8(7.62,2.54)
  silkscreen extent -1.47,-1.43 9.02,3.97, body extent -1.3,-1.3 8.86,3.78, height 8.5
"Header M 2x8x2.54 TH V" [mm] "2x8x2.54 Header TH V Male"
  rect 1.8x1.8 hole 1: 1(0,0)
  round 1.8 hole 1: 2(0,2.54) 3(2.54,0) 4(2.54,2.54) 5(5.08,0) 6(5.08,2.54) 7(7.62,0) 8(7.62,2.54) 9(10.16,0) 10(10.16,2.54) 11(12.7,0) 12(12.7,2.54) 13(15.24,0) 14(15.24,2.54) 15(17.78,0) 16(17.78,2.54)
  silkscreen extent -1.47,-1.43 19.15,3.97, body extent -1.32,-1.27 19,3.81, height 8.5
"Header M 2x19x2.54 TH M_top + M_bottom" [mm] "2x19x2.54 Header TH V MaleTop + MaleBottom (Morphos_Nucleo64)"
  rect 1.8x1.8 hole 1: 1(0,0)
  round 1.8 hole 1: 2(0,2.54) 3(2.54,0) 4(2.54,2.54) 5(5.08,0) 6(5.08,2.54) 7(7.62,0) 8(7.62,2.54) 9(10.16,0) 10(10.16,2.54) 11(12.7,0) 12(12.7,2.54) 13(15.24,0) 14(15.24,2.54) 15(17.78,0) 16(17.78,2.54) 17(20.32,0) 18(20.32,2.54) 19(22.86,0) 20(22.86,2.54) 21(25.4,0.127) 22(25.4,2.667) 23(27.94,0.127) 24(27.94,2.667) 25(30.48,0.127) 26(30.48,2.667) 27(33.02,0.127) 28(33.02,2.667) 29(35.56,0.127) 30(35.56,2.667) 31(38.1,0) 32(38.1,2.54) 33(40.64,0) 34(40.64,2.54) 35(43.18,0) 36(43.18,2.54) 37(45.72,0) 38(45.72,2.54)
  silkscreen extent -1.47,-1.43 47.24,3.97, body extent -1.32,-1.24 46.94,3.84, height 8.38
"Header NF 1x2x2.54 TH" [mm] "1x2x2.54 Header TH Not Fitted"
  rect 1.8x1.8 hole 1: 1(0,0)
  round 1.8 hole 1: 2(2.54,0)
  silkscreen extent -1.4,-1.4 3.94,1.4
"Header NF 1x5x2.54 TH" [mm] "1x5x2.54 Header TH Not Fitted"
  rect 1.8x1.8 hole 1: 1(0,0)
  round 1.8 hole 1: 2(2.54,0) 3(5.08,0) 4(7.62,0) 5(10.16,0)
  silkscreen extent -1.4,-1.4 11.56,1.4
"Header NF 1x6x2.54 TH" [mm] "1x6x2.54 Header TH Not Fitted"
  rect 1.8x1.8 hole 1: 1(0,0)
  round 1.8 hole 1: 2(2.54,0) 3(5.08,0) 4(7.62,0) 5(10.16,0) 6(12.7,0)
  silkscreen extent -1.4,-1.4 14.1,1.4
HSMF-A201 [mm] "LED"
  rect 1.5x1.1 smd: 1(-1.5,0.75) 2(1.5,0.75) 3(1.5,-0.75) 4(-1.5,-0.75)
  silkscreen extent -2.3,-1.55 1.75,1.93, body extent -1.6,-1.4 1.6,1.4, height 1.3
"Jumper 2.54mm BLACK" [mm] "Jumper 2.54mm Black"
  body extent -2.5,-1.2 2.5,1.2, height 8.5
LFB182G45CGFD436 [mm] "Band Pass Filter Murata LFB182G45CGFD436"
  rect 0.28x0.55 smd mask-0.01: 1(-0.56,0) 3(0.56,0)
  rect 0.4x0.6 smd mask-0.01: 2(0,0)
  silkscreen extent -0.8,-0.4 0.8,0.4, body extent -0.79,-0.39 0.8,0.39, height 0.66
"LOGO CE" [mm]
  silkscreen extent -3.27,-3.31 4.33,3.3
"LOGO ESD" [mm]
  silkscreen extent -3.23,-2.59 3.66,3.68
LOGO_Nucleo [mm] "LOGO_Nucleo Top Overlay"
  silkscreen extent -2.41,-3.86 2.77,1.98
LOGO_Nucleo_www [mm] "Web Link for STM32 Nucleo Board"
LOGO_ST_Size3 [mm]
  silkscreen extent -4.5,-2.36 4.7,2.57
LOGO_StickerArea_Border [mm] "Sticker Area reservation 22x6 mm Border only"
  silkscreen extent 0,0 22,6
LOGO_STM32 [mm]
  silkscreen extent -3.9,-4.23 4.33,3.95
LQFP48_7X7_P050 [mm]
  rect 0.3x1.2 smd mask+0.05: 1(-2.75,-4.25) 2(-2.25,-4.25) 3(-1.75,-4.25) 4(-1.25,-4.25) 5(-0.75,-4.25) 6(-0.25,-4.25) 7(0.25,-4.25) 8(0.75,-4.25) 9(1.25,-4.25) 10(1.75,-4.25) 11(2.25,-4.25) 12(2.75,-4.25) 25(2.75,4.25) 26(2.25,4.25) 27(1.75,4.25) 28(1.25,4.25) 29(0.75,4.25) 30(0.25,4.25) 31(-0.25,4.25) 32(-0.75,4.25) 33(-1.25,4.25) 34(-1.75,4.25) 35(-2.25,4.25) 36(-2.75,4.25)
  rect 1.2x0.3 smd mask+0.05: 13(4.25,-2.75) 14(4.25,-2.25) 15(4.25,-1.75) 16(4.25,-1.25) 17(4.25,-0.75) 18(4.25,-0.25) 19(4.25,0.25) 20(4.25,0.75) 21(4.25,1.25) 22(4.25,1.75) 23(4.25,2.25) 24(4.25,2.75) 37(-4.25,2.75) 38(-4.25,2.25) 39(-4.25,1.75) 40(-4.25,1.25) 41(-4.25,0.75) 42(-4.25,0.25) 43(-4.25,-0.25) 44(-4.25,-0.75) 45(-4.25,-1.25) 46(-4.25,-1.75) 47(-4.25,-2.25) 48(-4.25,-2.75)
  silkscreen extent -4.52,-4.53 3.52,3.52, body extent -4.5,-4.5 4.5,4.5, height 1.6
NX2012_2P [mm]
  rect 1x1.25 smd: 1(0,0) 2(1.5,0)
  silkscreen extent 0.63,-0.76 0.89,0.76, body extent -0.33,-0.76 1.88,0.76, height 0.75
NX2016_4P [mm]
  rect 0.85x0.75 smd: 1(-0.675,-0.525) 2(0.675,-0.525) 3(0.675,0.525) 4(-0.675,0.525)
  silkscreen extent -1.07,-1.16 1.02,0.81, body extent -1,-0.8 1,0.8, height 0.7
SB-tiny [mil]
  round 10 smd paste-10 mask+0.04: 1(-19.69,0)
  round 10 smd paste-10.08 mask+0.04: 2(20,0)
  L1 region: -5.91,19.69 13.78,0 -5.91,-19.68 25,-19.68 25,19.69
  L1 region: -30,-19.68 -30,19.69 -15.75,19.69 3.94,0 -15.75,-19.68
  silkscreen extent -32,-23 27,23
"Shield 17.2x17.2x3" [mm] "Metallic Shield 17.2x17.2mm height =3mm tickness=0.2mm"
  silkscreen extent 17.81,28.6 35.08,45.75, body extent 17.84,28.6 35.04,45.8, height 3
"Shield Clip_A 3.9x1.1x1.28" [mm] "Shield Clip 3.9x1.1x1.28 - Harwin S0951-46R - Full pad"
  rect 0.48x0.5 smd mask+0.075: 1(-1.81,0) 1(1.81,0)
  rect 0.7x0.5 smd mask+0.075: 1(-1.1,0) 1(1.1,0)
  rect 1.1x1.2 smd mask+0.075: 1(0,0)
  body extent -1.95,-0.55 1.95,0.55, height 1.28
SMA_T_9.52_NF [mm]
  rect 2.5x0.5 smd: 1(-2.413,0)
  rect 4.9x1.2 smd: 2(-3.556,-4.25) 2(-3.556,4.25)
  rect 4.9x1.2 smd far side: 2(-3.556,-4.25) 2(-3.556,4.25)
SOD523 [mm]
  rect 0.65x0.3 smd mask+0.05: A(-0.675,0) K(0.675,0)
  silkscreen extent -0.81,-0.41 0.91,0.41, body extent -0.81,-0.41 0.81,0.41, height 0.62
SOD-323 [mm] "Diode"
  rect 1.35x0.4 smd: 1(-1.2,0) 2(1.2,0)
  silkscreen extent -1.4,-0.75 1.94,0.75, body extent -1.35,-0.72 1.35,0.72, height 1.17
SOT23-3 [mm]
  rect 0.9x0.95 smd: 1(-0.95,-2.35) 2(0.95,-2.35) 3(0,0)
  silkscreen extent -1.9,-3.35 1.3,0, body extent -1.46,-2.42 1.46,0.06, height 1.1
SOT23-5 [mil]
  rect 50x20 smd: 1(-50,37.5) 2(-50,0.5) 3(-50,-37.5) 4(50,-37.5) 5(50,37.5)
  silkscreen extent -104,-8 55,77, body extent -55,-57 55,57, height 57
SOT23-6 [mm]
  rect 1.27x0.508 smd: 1(0,0) 2(0,-0.95) 3(0,-1.9) 4(2.3,-1.9) 5(2.3,-0.95) 6(2.3,0)
  silkscreen extent -1.37,0.13 -0.51,1, body extent -0.02,-2.39 2.32,0.53, height 1
SOT223_SC73_A [mm]
  rect 1.5x1.65 smd mask+0.05: 1(-2.3,-3.175) 2(0,-3.175) 3(2.3,-3.175)
  rect 3.5x1.65 smd mask+0.05: 2(0,3.175)
  silkscreen extent -3.35,-2.15 3.35,2.12, body extent -3.35,-3.48 3.35,3.48, height 1.8
SOT353-1 [mm] "SOT353-1 5 pins package"
  rect 0.8x0.37 smd mask+0.075: 1(-0.076,0) 2(-0.076,-0.65) 3(-0.076,-1.3) 4(1.951,-1.3) 5(1.951,0)
  silkscreen extent -0.38,-1.7 1.91,0.51, body extent -0.31,-1.73 2.09,0.47, height 1.1
Sticker_BrdRef_21x5mm [mm] "Sticker_BrdRef_21x5mm White"
  silkscreen extent 0,0 21,5, body extent 0,0 21,5, height 0.1
"Sticker_CPN_FG 16x5mm" [mm] "Sticker_CPN_FG 16x6mm White"
  silkscreen extent 0,0 16,5, body extent 0,0 16,5, height 0.1
"Sticker_FCC_ID 16x5mm" [mm] "Sticker_FCC_ID 16x5mm White"
  silkscreen extent 0,0 16,5, body extent 0,0 16,5, height 3.1
"SW-PB SMD KMR2" [mm]
  rect 0.9x1 smd: 1(-2.05,0.8) 1(2.05,0.8) 2(-2.05,-0.8) 2(2.05,-0.8)
  silkscreen extent -2.4,-1.52 2.42,1.53, body extent -2.41,-1.52 2.41,1.52, height 2.52
SYMBOL_RoHS [mm]
  silkscreen extent 0,0 9.5,6
TSSOP20 [mm]
  rect 1.55x0.25 smd: 1(0,0)
  oval 1.55x0.25 smd: 2(0,-0.65) 3(0,-1.3) 4(0,-1.95) 5(0,-2.6) 6(0,-3.25) 7(0,-3.9) 8(0,-4.55) 9(0,-5.2) 10(0,-5.85) 11(5.6,-5.85) 12(5.6,-5.2) 13(5.6,-4.55) 14(5.6,-3.9) 15(5.6,-3.25) 16(5.6,-2.6) 17(5.6,-1.95) 18(5.6,-1.3) 19(5.6,-0.65) 20(5.6,0)
  silkscreen extent -0.77,-6.27 5.64,0.61, body extent -0.43,-6.17 5.97,0.33, height 1.2
USBMICROB_MOLEX_105017-0001_H2P90 [mm]
  rect 0.4x1.35 smd mask+0.05: 1(-1.3,4.15) 2(-0.65,4.15) 3(0,4.15) 4(0.65,4.15) 5(1.3,4.15)
  oval 1.2x1.9 hole 0.6 slot 1.3 at 90 deg mask+0.05: 6(-3.5,1.45) 6(3.5,1.45)
  round 1.5 hole 0.9 mask+0.05: 6(-2.5,4.15) 6(2.5,4.15)
  rect 1.5x1.9 smd mask+0.05: 6(-1,1.45) 6(1,1.45)
  L1 region: -3.5,2.4 -2.3,2.4 -2.3,0.5 -3.5,0.5
  L1 region: 2.3,2.4 3.5,2.4 3.5,0.5 2.3,0.5
  silkscreen extent -4.45,0 4.45,5.3, body extent -4.1,-1.15 4.1,4.66, height 2.9
VFQFPN68_8x8x0.1_p0.4 [mm]
  oct 1x0.25 smd mask+0.04: 1(-3.878,3.2) 2(-3.878,2.8) 3(-3.878,2.4) 4(-3.878,2) 5(-3.878,1.6) 6(-3.878,1.2) 7(-3.878,0.8) 8(-3.878,0.4) 9(-3.878,0) 10(-3.878,-0.4) 11(-3.878,-0.8) 12(-3.878,-1.2) 13(-3.878,-1.6) 14(-3.878,-2) 15(-3.878,-2.4) 16(-3.878,-2.8) 17(-3.878,-3.2) 35(3.903,-3.2) 36(3.903,-2.8) 37(3.903,-2.4) 38(3.903,-2) 39(3.903,-1.6) 40(3.903,-1.2) 41(3.903,-0.8) 42(3.903,-0.4) 43(3.903,0) 44(3.903,0.4) 45(3.903,0.8) 46(3.903,1.2) 47(3.903,1.6) 48(3.903,2) 49(3.903,2.4) 50(3.903,2.8) 51(3.903,3.2)
  oct 0.25x1 smd mask+0.04: 18(-3.2,-3.903) 19(-2.8,-3.903) 20(-2.4,-3.903) 21(-2,-3.903) 22(-1.6,-3.903) 23(-1.2,-3.903) 24(-0.8,-3.903) 25(-0.4,-3.903) 26(0,-3.903) 27(0.4,-3.903) 28(0.8,-3.903) 29(1.2,-3.903) 30(1.6,-3.903) 31(2,-3.903) 32(2.4,-3.903) 33(2.8,-3.903) 34(3.2,-3.903) 52(3.2,3.903) 53(2.8,3.903) 54(2.4,3.903) 55(2,3.903) 56(1.6,3.903) 57(1.2,3.903) 58(0.8,3.903) 59(0.4,3.903) 60(0,3.903) 61(-0.4,3.903) 62(-0.8,3.903) 63(-1.2,3.903) 64(-1.6,3.903) 65(-2,3.903) 66(-2.4,3.903) 67(-2.8,3.903) 68(-3.2,3.903)
  rect 6.5x6.5 smd paste-5 mask-0.01: 69(0,0)
  silkscreen extent -5.14,-4 4,5.07, body extent -4.01,-3.99 3.99,3.99, height 1.2
X3225 [mm]
  rect 1.4x1.15 smd paste-2 mask-2: 1(-1.1,-0.8) 2(1.1,-0.8) 4(-1.1,0.8)
  rect 1.4x1.15 smd paste-1 mask-1: 3(1.1,0.8)
  silkscreen extent -1.7,-1.3 1.7,1.3, body extent -1.6,-1.24 1.6,1.26, height 0.61

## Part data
C1 C2 C3 C4 C5 C6 C7 C8 C12 C13 C14 C15 C16 C17 C18 C19 C20 C21 C22 C23 C24 C25 C26 C27 C28 C29 C31 C32 C33 C34 C35 C36 C37 C38 C39 C40 C41 C42 C43 C44 C45 C46 C47 C48 C49 C50: library part CAP_NPOL, "Capacitor_not polarized"
C9 C10 C11: library part CAP_POL, "Condensateur_polarise"
CN1 CN15: "USB-MICRO-B, 1050170001, SMT, MOLEX"
CN6 CN9: library part HEADER_1X8
CN7 CN10: library part HEADER_2X19
D1: library part BAT54K, "Schottky Diode"
D2: library part Diode, "Default Diode"
FLT1: "Band Pass Filter Murata LFB182G45CGFD436"
JP2 JP3 JP4 JP6: library part HEADER_1X2_L
L1: library part IND_74479777310A, "Coil Wurtz 10uH ref: 74479777310A"
L2: library part IND_FCM1608KF-601T03
L3 L4 L5: library part INDUCTOR_SMD_STDL
LED1 LED2 LED3 LED4 LED5: library part LED, "Light-Emitting Diode"
LED6: library part LD_BICOLOR_CMS, "Bicolor Led"
Q1: "2N2222_SOT23"
R1 R2 R3 R4 R5 R6 R7 R8 R9 R10 R11 R12 R14 R15 R16 R17 R18 R19 R20 R21 R22 R23 R24 R25 R26 R27 R28 R29 R30 R31 R32 R33: library part RES, "Resistor"
SB1 SB2 SB3 SB4 SB5 SB6 SB7 SB8 SB9 SB10 SB11 SB12 SB13 SB14 SB15 SB16 SB17 SB18 SB22 SB23 SB24 SB25 SB26 SB27 SB28 SB29 SB30 SB31 SB32 SB33 SB34 SB35 SB36 SB37 SB38 SB39 SB40 SB41 SB42 SB43 SB44 SB45 SB46 SB47 SB48 SB49 SB50 SB51: library part Strap2, "Solder Jumper"
SC1 SC2 SC3 SC4: "Harwin S0951-46R"
SH1: library part Shield, "Shield"
STICKER_1: library part LOGO_Sticker_FCC_ID, "Sticker for FCC_ID 16x5mm"
STICKER_2: library part LOGO_Sticker_BrdRef, "Sticker_BrdRef 21x5mm"
STICKER_3: library part LOGO_Sticker_CPN_FG, "Sticker for CPN_FG 16x5mm"
SW1 SW2 SW3 SW4: library part SW-PB_1, "Push-button SMD"
U2: "IC REG LDO 5V 0.8A SOT223"
U3: "3.3V voltage regulator 500mA"
U4: "Enhanced single channel power switches"
U5: "3.3V low drop voltage regulator"
U6 U9: library part USBLC6-2
U7: "TXS0108E Bi-directional Level Shifter TSSOP20"
U8: "Medium-density performance line ARM-based 32-bit MCU with 128KB Flash"
X1: "Crystal NDK 2.0x1.6mm  32 MHz"
X2: "Crystal NDK 2.0x1.2mm  32.768 KHz"
X3: library part X3225, "Crystal 8MHz"

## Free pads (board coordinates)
  round 0.4 hole 0.3: 2(17.124,1.163) 3(22.655,1.163) 4(28.212,1.181) 5(28.212,1.181) 6(42.738,7.684) 7(36.649,6.653) 8(38.51,5.064) 9(53.505,8.717) 10(53.505,8.297) 11(51.303,6.754) 12(53.3,9.344) 13(53.751,9.347) 14(54.598,16.576) 15(54.877,13.95)
  round 0.3 hole 0.2: 16(52.372,11.445) 17(52.362,11.915) 18(54.429,12.296) 19(50.454,13.279) 21(38.602,7.671) 22(49.477,10.329) 23(14.157,3.363) 24(18.268,3.349) 25(19.535,3.349) 26(29.478,22.894) 27(28.68,18.577) 28(38.019,25.374) 29(38.019,25.374) 30(34.505,12.567) 31(34.311,10.698) 32(35.416,11.407) 33(36.014,11.398) 34(36.907,11.941) 35(33.814,16.645) 36(31.761,14.657) 37(41.842,16.111) 38(41.253,17.115) 39(43.674,17.115) 40(43.665,15.596) 41(50.79,20.098) 42(49.464,14.316) 43(40.065,15.08) 45(40.139,20.466) 46(41.768,20.006) 47(40.05,17.173) 48(40.056,16.1) 49(35.633,20.556) 50(35.61,19.894) 51(35.633,19.262) 52(35.633,18.585) 53(36.479,16.658) 54(50.398,9.517) 55(46.514,20.37) 56(54.174,20.99) 57(54.406,18.743) 58(54.398,17.561) 59(53.716,21.644) 60(47.18,26.465) 61(48.123,26.473) 62(45.254,26.469) 63(44.124,26.477) 64(53.56,30.734) 65(53.56,30.734) 66(22.419,48.776) 67(21.991,48.937) 69(21.391,48.926) 70(23.244,48.739) 71(23.64,48.996) 72(24.042,48.749) 73(24.428,48.985) 74(24.851,48.728) 75(25.21,49.012) 76(25.643,48.739) 77(26.05,48.985) 79(26.441,48.739) 80(26.816,48.99) 81(27.239,48.728) 82(27.689,48.937) 83(28.262,48.835) 85(20.318,44.67) 86(19.88,42.678) 87(19.866,42.196) 89(19.863,40.906) 90(20.277,40.704) 91(20.937,40.547) 92(46.464,22.812) 93(52.166,20.106) 94(15.544,11.429) 95(20.006,46.652) 96(19.997,47.142) 97(29.483,41.309) 99(29.533,42.652) 100(29.534,43.063) 101(29.678,43.448) 102(29.411,43.845) 103(29.698,44.254) 104(29.402,44.656) 105(54.205,44.276) 106(54.225,43.816) 107(18.983,42.514) 108(16.702,43.63) 109(37.844,34.004) 110(30.058,40.815) 111(18.692,49.362) 112(18.681,50.398) 113(18.358,48.315) 114(17.648,47.219) 115(18.608,47.25) 116(28.166,39.644) 117(35.008,35.615) 118(36.254,34.908) 119(30.039,39.083) 120(30.889,39.705) 121(30.951,45.052) 122(30.592,46.046) 124(20.112,43.131) 125(22.518,46.172) 126(23.269,46.196) 127(35.925,49.364) 128(18.464,26.334) 129(34.813,42.126) 130(29.237,30.345) 131(32.301,32.41) 132(62.308,28.747) 133(62.308,28.747) 134(30.49,42.607) 135(20.21,39.106) 136(26.249,39.108) 138(28.786,39.28) 139(22.72,54.855) 140(19.541,54.935) 141(27.98,52.47) 142(27.027,51.622) 143(29.923,50.322) 144(28.946,49.456) 145(34.603,50.003) 146(39.908,51.319) 147(33.099,51.917) 148(34.115,51.891) 149(42.147,51.814) 150(42.878,51.803) 151(43.633,55.306) 152(43.599,53.084) 153(41.596,54.415) 154(41.596,52.902) 155(35.869,56.698) 155(39.794,56.684) 156(37.563,56.55) 156(41.596,56.684) 157(32.576,56.7) 158(33.099,52.528) 158(33.099,53.922) 159(22.848,51.355) 160(26.07,51.42) 161(36.77,56.698) 161(40.695,56.684) 162(33.099,55.315) 163(33.099,54.618) 164(33.099,56.012) 165(33.143,56.674) 166(34.968,56.698) 166(37.54,55.94) 166(38.933,56.017) 166(38.943,56.504) 168(41.596,55.928) 169(41.596,55.171) 170(43.546,56.223) 171(43.536,54.335) 172(41.288,51.549) 173(40.545,51.72) 174(41.578,52.146) 175(41.596,53.659) 176(39.838,51.941) 177(43.608,53.468) 178(43.567,53.932) 179(43.608,54.861) 180(43.515,55.821) 181(43.536,56.595) 182(34.968,55.919) 182(37.54,55.191) 182(38.933,55.238) 183(34.968,53.583) 183(37.54,52.942) 183(38.933,52.902) 184(34.968,55.141) 184(37.54,54.441) 184(38.933,54.46) 185(34.968,54.362) 185(37.54,53.691) 185(38.933,53.681) 186(34.942,52.018) 186(34.968,52.805) 186(37.62,52.145) 187(35.76,50.551) 188(36.861,52.001) 189(33.099,53.225) 190(38.941,52.143) 191(35.991,51.967) 192(52.23,21.133) 193(44.164,20.067) 194(41.793,22.048) 195(43.443,22.029) 196(39.955,23.801) 197(53.21,21.19) 198(50.495,22.236) 199(19.056,15.66) 200(19.056,14.294) 201(19.056,12.929) 202(19.056,11.563) 203(19.056,10.198) 204(19.073,9.213) 205(19.073,8.236) 206(19.073,7.259) 207(19.223,6.257) 208(20.025,5.355) 209(48.167,14.72) 210(46.489,14.599) 211(46.475,15.386) 212(46.418,16.328) 213(7.344,12.685) 214(9.625,13.458) 215(15.178,11.874) 216(13.415,14.665) 217(12.67,13.826) 218(8.437,13.411) 219(8.579,11.95) 220(9.757,11.846) 221(7.325,13.458) 222(13.82,9.461) 223(14.772,10.243) 224(12.444,10.319) 225(13.735,22.565) 226(14.216,29.325) 227(38.027,34.831) 228(40.302,35.528) 229(39.209,47.944) 230(39.605,46.813) 231(39.511,45.738) 232(46.11,46.012) 233(45.243,49.264) 234(46.063,48.444) 235(48.222,48.538) 236(48.193,46.341) 237(49.315,46.323) 238(50.381,46.247) 239(50.381,46.247) 241(49.268,49.198) 242(49.956,48.793) 243(7.107,15.822) 244(8.58,15.807) 245(9.719,15.822) 246(9.704,14.532) 247(7.046,14.426) 248(7.957,14.532) 249(12.072,14.836) 250(12.072,14.836) 251(11.996,15.914) 254(12.107,12.089) 255(40.993,6.108) 256(41.751,6.108) 257(57.145,7.287) 258(57.821,6.847) 259(60.619,7.381) 260(60.698,8.246) 261(60.572,9.614) 262(62.239,9.504) 263(63.009,9.535) 264(62.899,8.262) 265(61.83,7.711) 266(60.478,32.585) 267(60.462,34.786) 268(60.368,36.327) 269(55.903,30.619) 270(54.22,30.211) 271(54.252,31.358) 272(57.585,29.912) 273(57.695,32.239) 274(57.852,34.11) 275(57.821,35.415) 276(56.689,37.978) 277(50.415,31.343) 278(50.415,29.676) 279(51.453,29.707) 280(51.437,31.374) 281(46.296,28.685) 282(47.318,28.733) 283(46.689,29.865) 284(28.997,29.561) 285(23.089,27.455) 286(24.436,27.455) 287(26.163,27.472) 288(27.163,27.496) 289(32.033,23.729) 290(34.759,23.253) 291(29.492,20.608) 292(29.479,19.178) 293(34.36,20.691) 294(34.287,18.312) 295(35.056,19.597) 296(35.099,18.384) 297(35.105,20.536) 298(34.323,19.482) 299(38.033,18.281) 300(38.154,19.948) 301(38.197,17.247) 302(38.153,16.746) 303(60.523,47.925) 304(60.332,48.952) 305(60.369,46.473) 306(57.75,48.057) 307(56.034,49.634) 308(57.875,50.419) 309(57.956,49.194) 310(16.201,43.041) 311(16.837,41.923) 312(18.027,43.293) 313(54.279,22.807) 314(57.797,23.315) 315(42.816,24.211) 316(43.74,24.226) 318(8.328,41.381) 319(9.399,40.104) 320(9.516,41.271) 321(10.433,43.801) 322(11.079,44.344) 323(10.448,45.026) 325(9.324,34.02) 326(9.35,35.067) 327(10.304,34.26) 328(11.617,34.273) 329(9.968,36.4) 330(9.657,36.033) 332(12.197,35.907) 333(12.151,34.86) 334(12.184,34.013) 335(8.377,31.615) 336(9.769,31.59) 337(11.39,31.691) 338(6.63,31.641) 339(6.959,45.339) 340(7.035,45.973) 342(58.981,25.54) 343(59.812,25.524) 344(61.507,25.46) 345(61.531,26.121) 346(62.755,18.958) 347(63.015,17.057) 348(18.239,31.675) 349(18.221,30.475) 350(18.245,28.929) 351(18.319,27.236) 352(18.649,24.894) 353(62.336,52.484) 354(60.253,51.805) 355(12.897,1.299) 356(12.04,2.243) 357(11.225,2.486) 358(9.882,2.486) 359(8.209,2.529) 360(8.009,3.529) 361(6.68,3.572) 362(5.179,3.658) 363(3.636,3.601) 364(2.664,3.543) 365(2.592,2.457) 366(8.818,27.856) 367(2.81,56.535) 368(4.965,56.556) 369(7.037,56.577) 370(9.067,56.577) 371(11.097,56.556) 372(13.315,56.577) 373(15.198,56.514) 374(15.198,56.514) 375(16.873,56.514) 376(18.902,56.514) 377(18.861,55.51) 378(20.409,55.426) 379(21.351,55.468) 380(22.23,55.573) 381(21.192,56.755) 382(23.586,56.761) 383(24.821,56.687) 384(26.349,56.677) 385(23.625,55.447) 386(24.59,55.295) 387(25.53,54.634) 388(26.47,53.72) 389(27.181,53.288) 390(28.273,53.136) 391(29.46,53.166) 392(29.485,54.433) 393(28.478,54.448) 394(27.638,54.533) 395(26.902,55.168) 396(25.86,56.184) 397(27.451,56.652) 398(28.698,56.617) 399(29.73,56.567) 400(30.407,56.532) 401(31.599,56.607) 402(30.686,54.279) 403(32.015,54.458) 404(32.19,53.516) 405(31.92,52.81) 406(32.421,52.048) 407(30.661,52.602) 408(31.372,51.078) 409(32.617,50.57) 410(34.039,50.52) 411(36.654,50.581) 412(37.646,50.591) 413(38.753,50.596) 414(39.434,50.566) 415(39.87,50.821) 416(28.781,52.247) 417(29.238,52.755) 418(29.775,51.337) 419(30.422,52.124) 420(30.915,51.561) 421(27.18,52.399) 422(29.667,49.695) 423(27.952,49.664) 424(27.206,50.541) 425(26.735,50.3) 426(25.472,50.354) 427(23.418,50.333) 429(24.161,50.323) 430(25.007,50.336) 431(21.596,50.149) 432(22.19,50.21) 433(22.239,50.919) 434(22.251,51.598) 435(21.511,51.61) 436(20.76,52.265) 437(20.166,52.762) 438(19.296,52.717) 439(17.937,52.681) 440(16.012,52.646) 441(14.724,52.717) 442(14.653,53.921) 443(14.642,55.138) 444(14.559,56.142) 445(16,55.256) 446(17.11,55.28) 447(18.114,55.327) 448(17.973,53.992) 449(17.973,53.992) 450(16.709,53.969) 451(15.598,53.981) 452(19.13,53.91) 453(20.808,53.862) 454(21.623,54.725) 455(22.213,53.697) 456(23.702,54.477) 457(23.796,54.819) 458(24.824,53.921) 459(25.899,53.732) 460(26.253,52.409) 461(25.048,51.464) 462(23.796,51.417) 463(28.607,55.516) 464(29.974,55.643) 465(31.341,55.643) 466(31.341,55.643) 467(30.86,50.173) 468(30.86,50.173) 469(32.152,50.224) 470(33.367,50.148) 471(44.255,51.997) 472(47.42,52.073) 473(50.079,52.199) 474(45.014,54.225) 475(40.685,50.68) 476(42.634,50.857) 477(69.474,52.984) 478(69.449,50.477) 479(62.57,14.419) 480(63.025,13.327) 481(65.65,13.834) 482(62.297,15.913) 483(63.09,15.796) 484(62.193,12.132) 485(63.051,10.806) 486(60.504,12.249) 487(60.595,13.236) 488(60.582,10.819) 489(62.687,6.635) 490(61.635,5.804) 491(61.946,4.115) 492(62.947,4.478) 493(65.533,5.674) 494(67.937,6.324) 495(67.846,8.87) 496(67.859,11.417) 497(67.742,13.847) 498(67.859,16.485) 499(67.859,19.057) 500(67.69,21.578) 501(65.637,21.461) 502(67.69,24.073) 503(67.625,26.723) 504(65.663,26.529) 505(65.52,28.595) 506(67.846,28.685) 507(65.468,30.712) 508(65.845,34.637) 509(67.69,34.351) 510(68.144,37.612) 511(67.235,36.741) 512(67.885,39.106) 513(65.533,39.249) 514(63.454,39.327) 515(65.611,41.887) 516(63.35,41.874) 517(67.794,41.861) 518(67.768,44.356) 519(67.729,46.915) 520(67.703,49.501) 521(67.794,52.295) 522(65.481,52.243) 523(61.245,53.191) 524(62.856,51.593) 525(64.259,52.685) 526(62.219,54.595) 527(51.617,47.123) 528(51.669,44.538) 529(52.968,47.149) 530(55.06,47.214) 531(53.033,45.954) 532(21.863,43.098) 533(22.777,42.184) 534(24.043,42.248) 535(24.018,41.505) 536(25.921,42.134) 537(25.888,41.475) 538(24.993,41.822) 539(27.043,42.196) 540(27.04,41.486) 541(22.754,43.088) 542(25.149,45.018) 543(25.915,45.044) 544(25.034,46.664) 545(26.133,46.653) 546(22.406,45.025) 547(23.057,45.02) 548(24.073,43.771) 549(24.598,43.14) 550(24.941,43.776) 551(25.442,43.418) 552(25.925,43.793) 553(25.975,43.157) 554(27.036,43.771) 555(27.064,43.14) 556(21.904,41.284) 557(23.968,46.643) 558(25.582,47.061) 559(22.421,42.7) 560(22.435,47.608) 561(27.679,43.682) 562(27.627,43.148) 563(27.731,42.118) 564(27.692,41.453) 565(12.724,54.295) 566(11.329,54.36) 567(10.938,53.669) 568(10.495,52.6) 569(11.773,48.715) 570(12.79,48.702) 571(9.999,48.702) 572(9.986,50.501) 573(13.129,51.179) 574(14.015,52.209) 575(13.454,55.181) 576(14.458,47.476) 577(15.2,46.445) 578(29.996,36.438) 580(28.937,36.434) 581(22.374,32.59)
  round 0.3 hole 0.2 mask-0.01: 585(37.828,35.375)

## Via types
v1: diameter 0.3, hole 0.2, L1 to L4, tented both sides, 254 vias
v2: diameter 0.406, hole 0.203, L1 to L4, tented both sides, 7 vias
